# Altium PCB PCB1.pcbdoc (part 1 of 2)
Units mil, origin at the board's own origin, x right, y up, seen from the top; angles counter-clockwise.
Board outline 3622 x 3621.7 mil, 4 copper layers (Top Layer, Inner1, Inner2, Bottom Layer), stack 62.5 mil thick; 107 components, 108 nets, 595 pads, 260 vias.
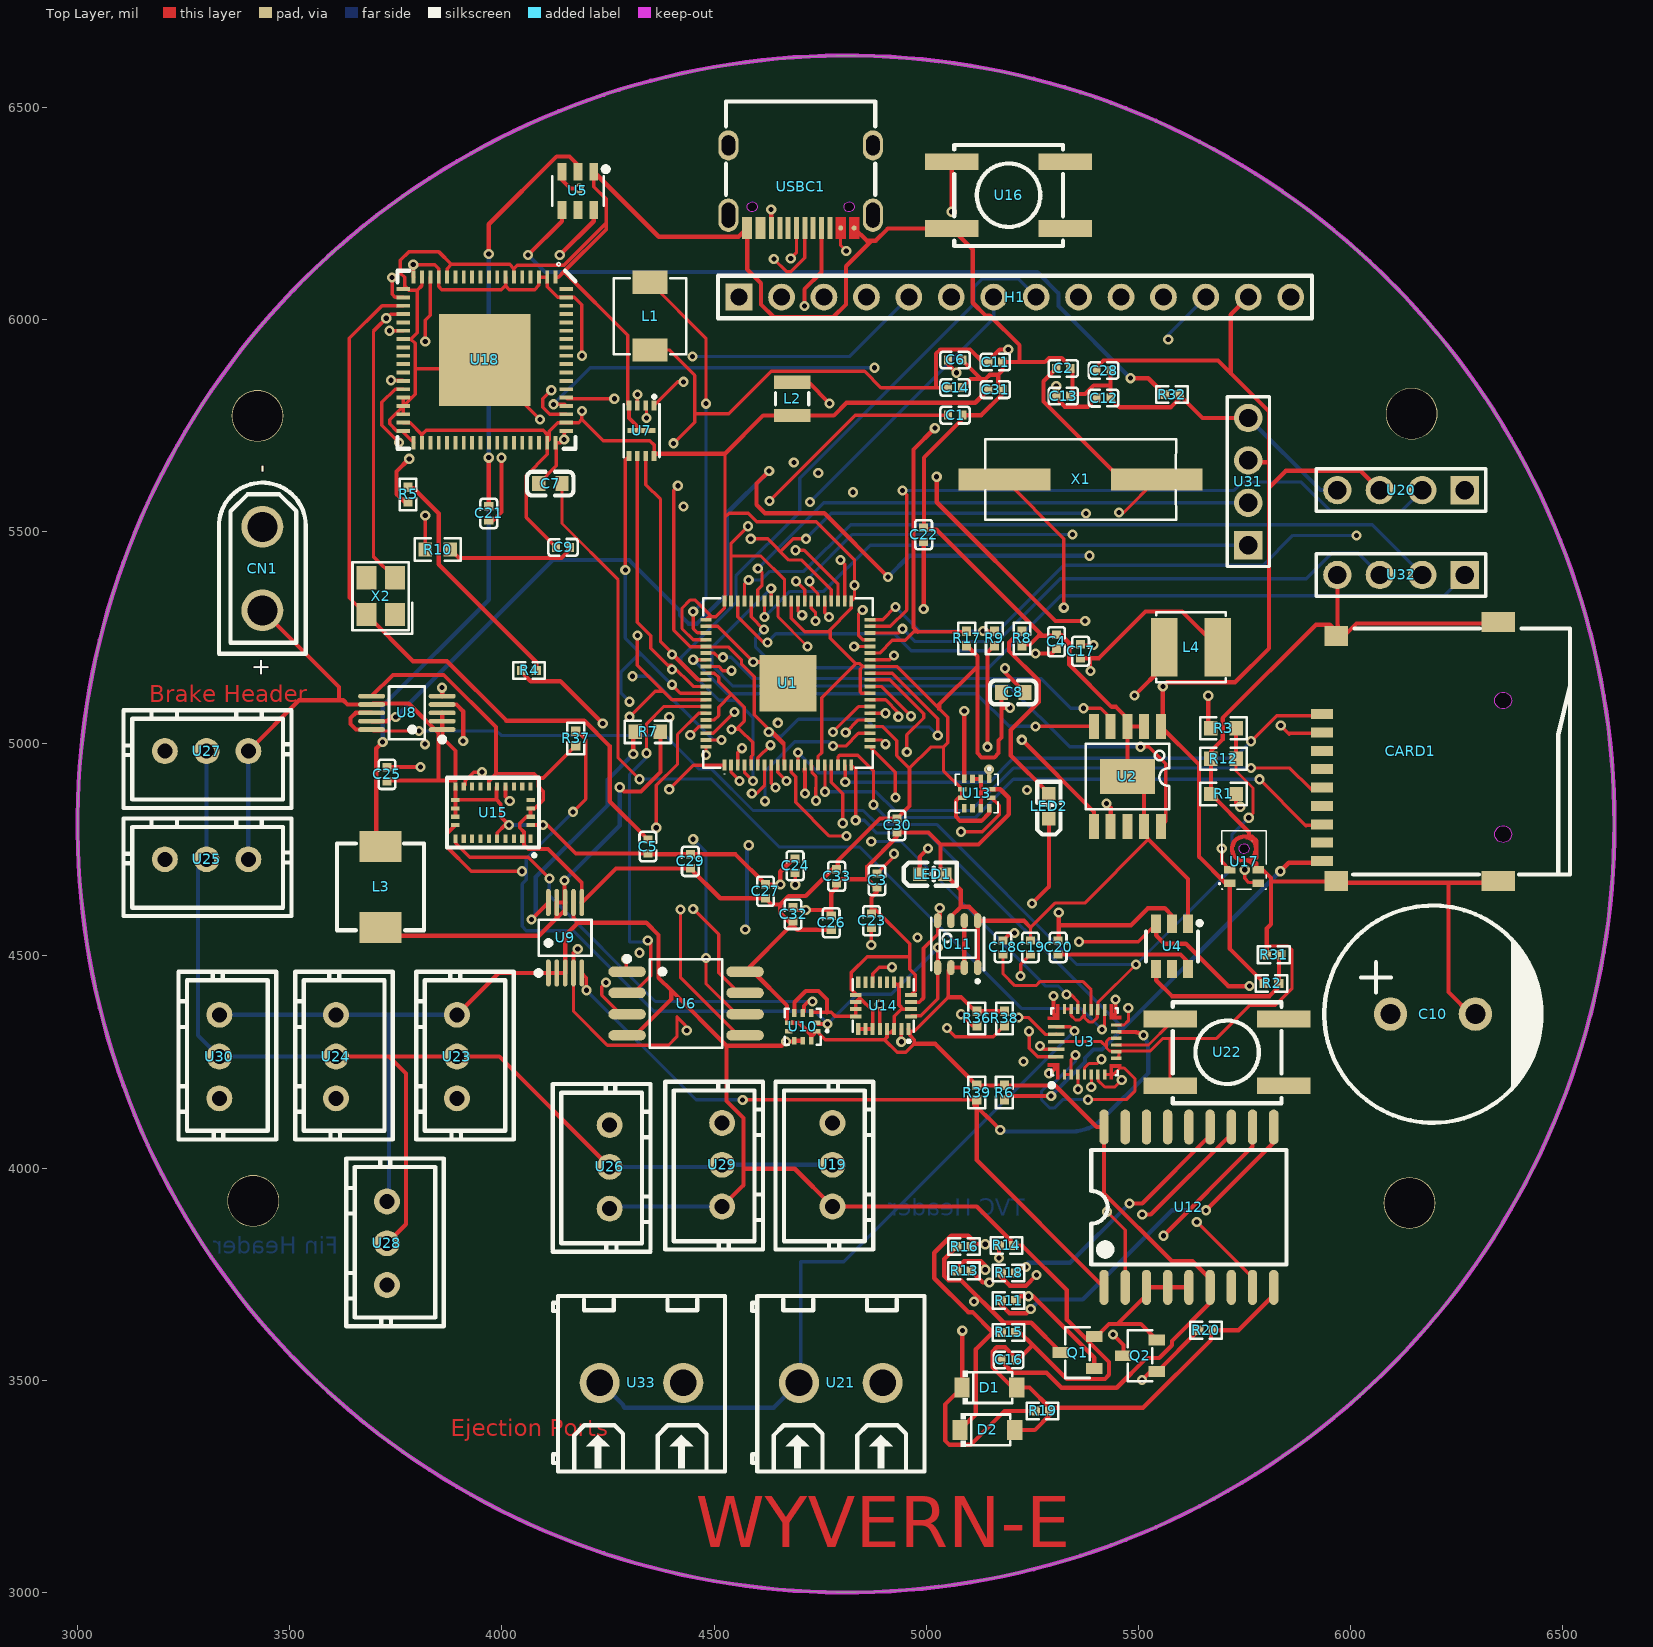
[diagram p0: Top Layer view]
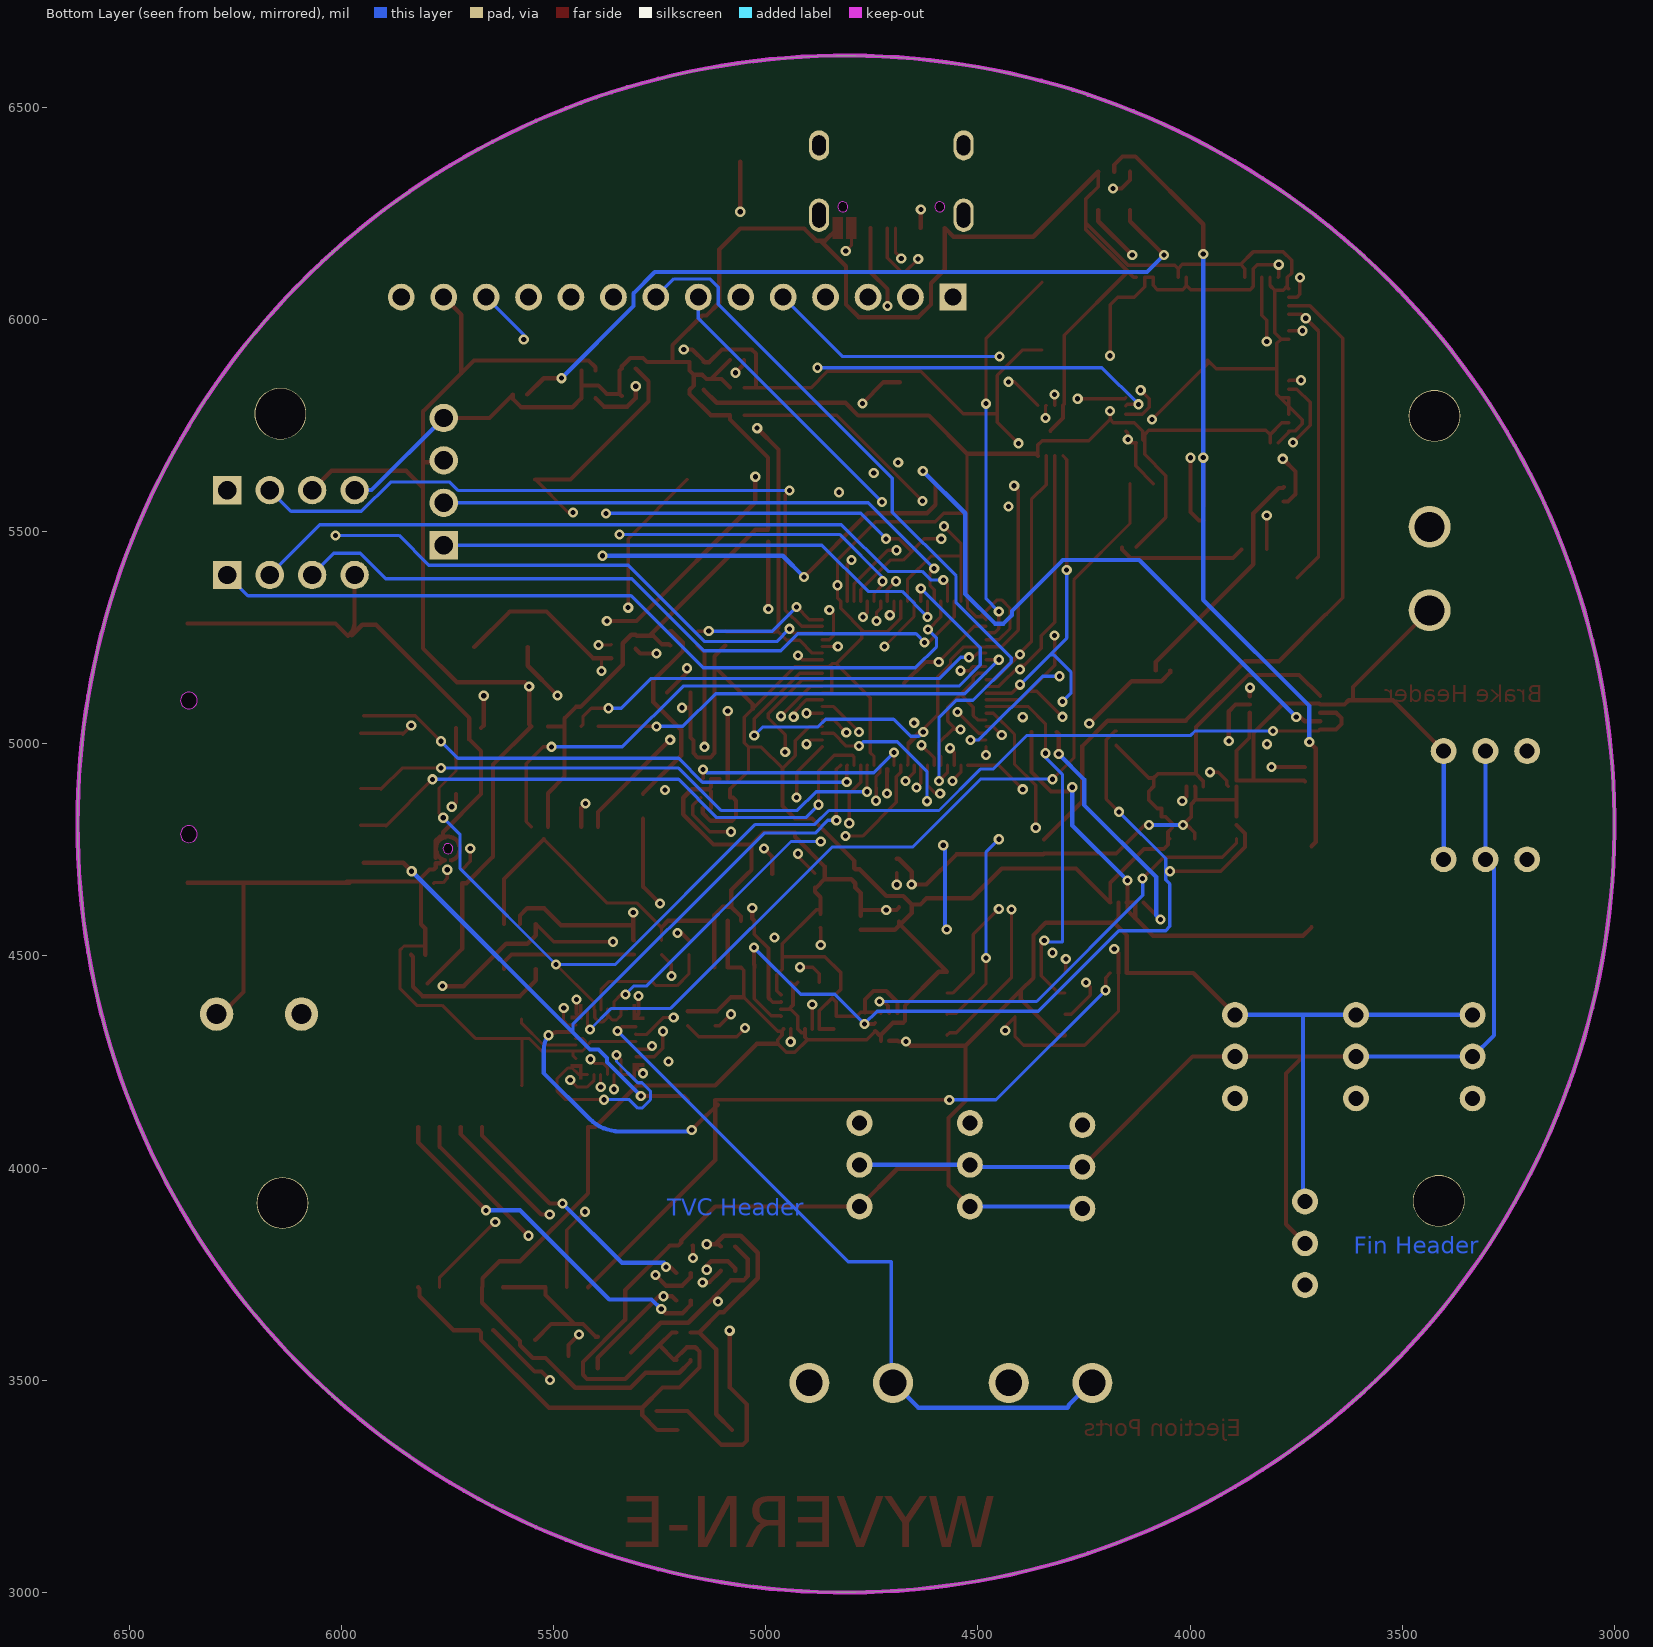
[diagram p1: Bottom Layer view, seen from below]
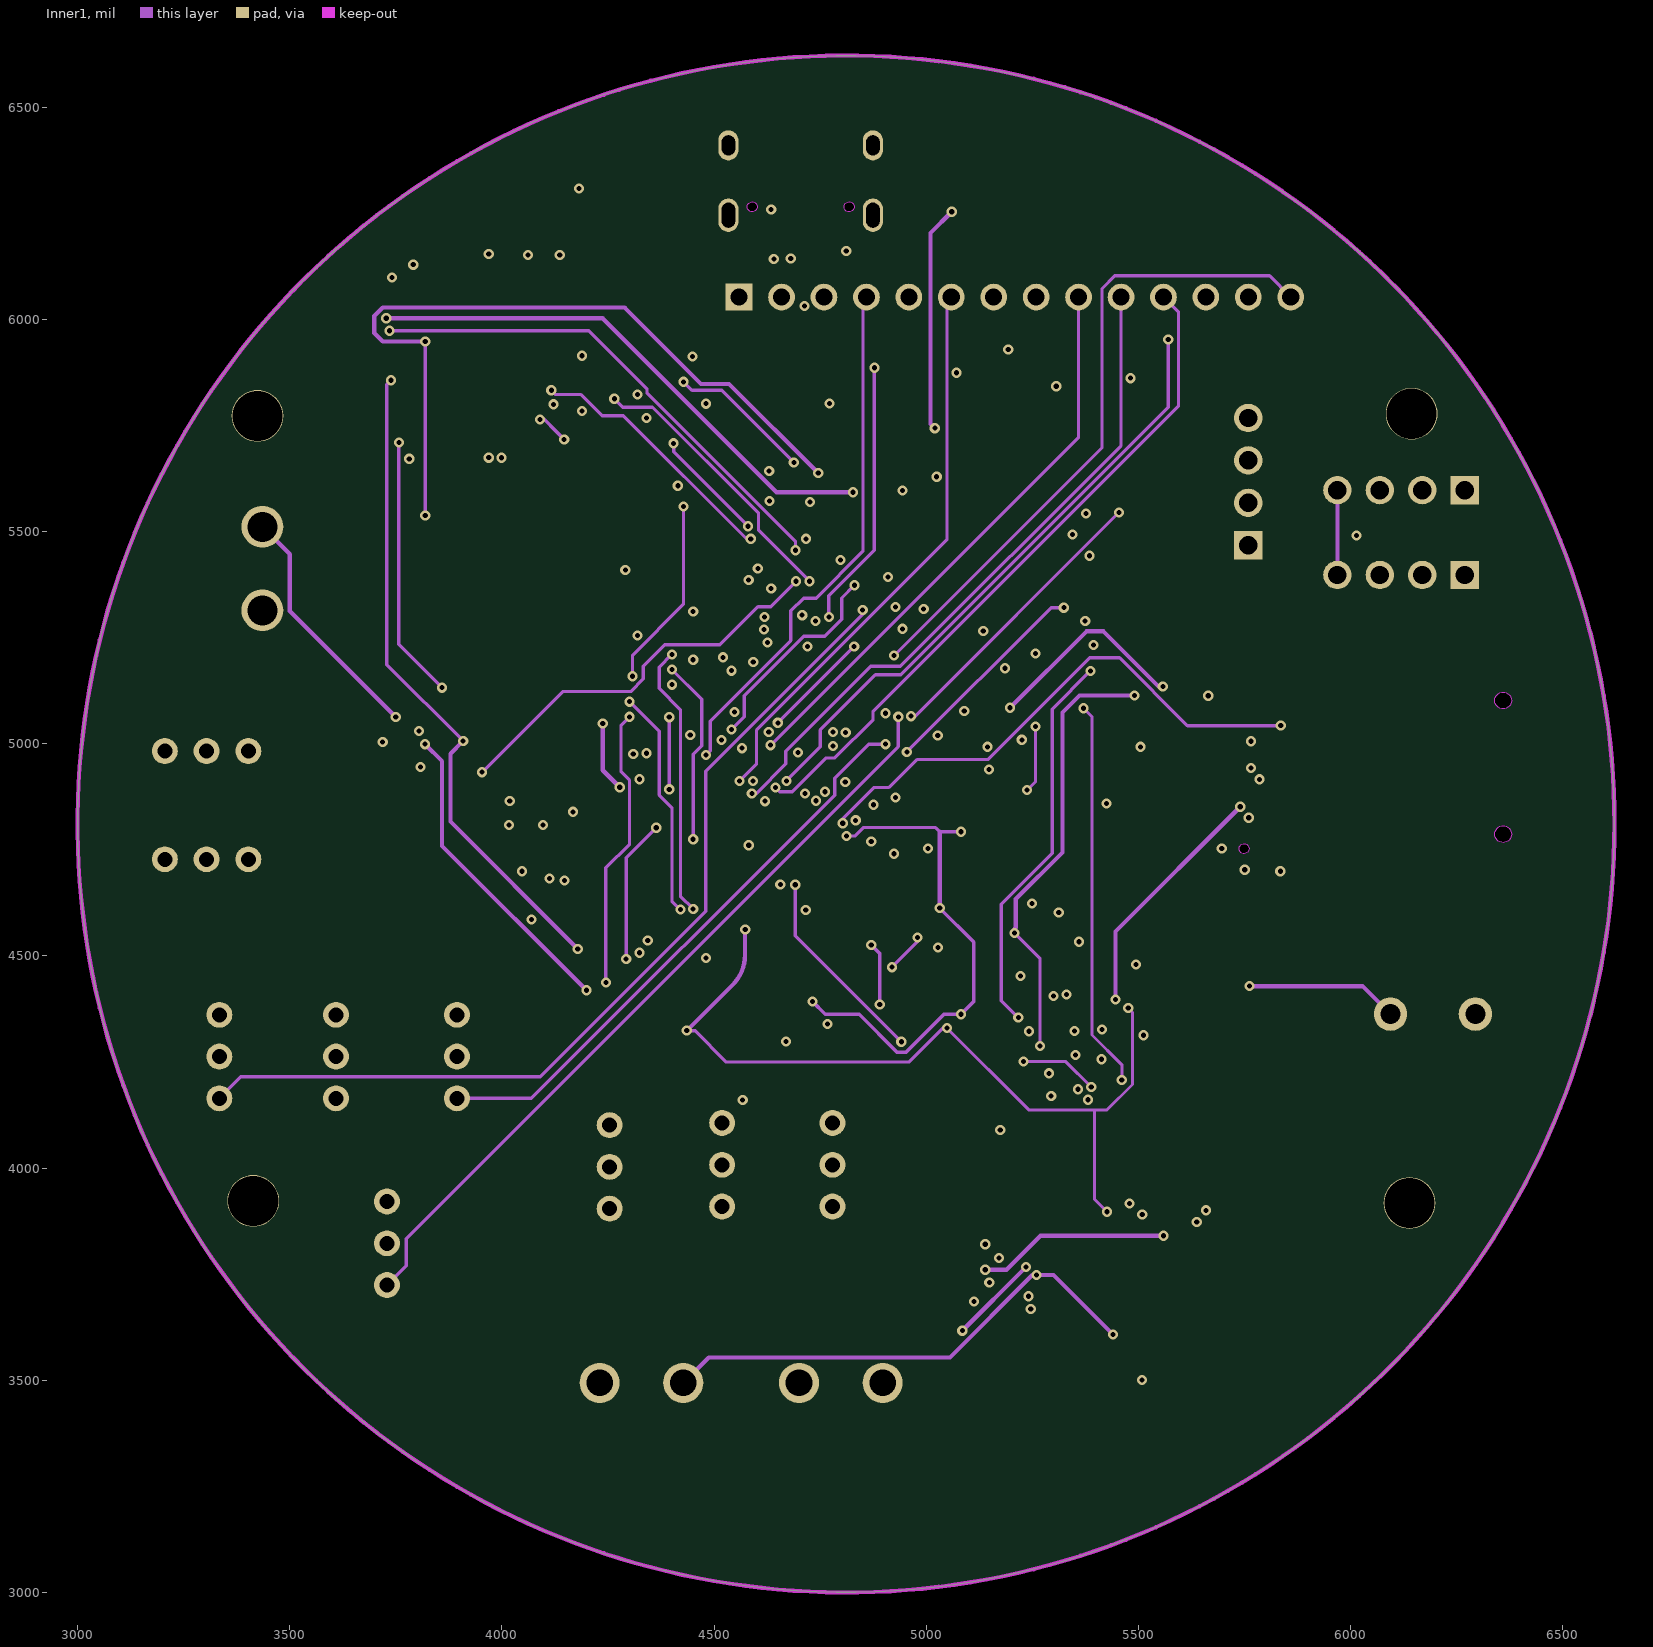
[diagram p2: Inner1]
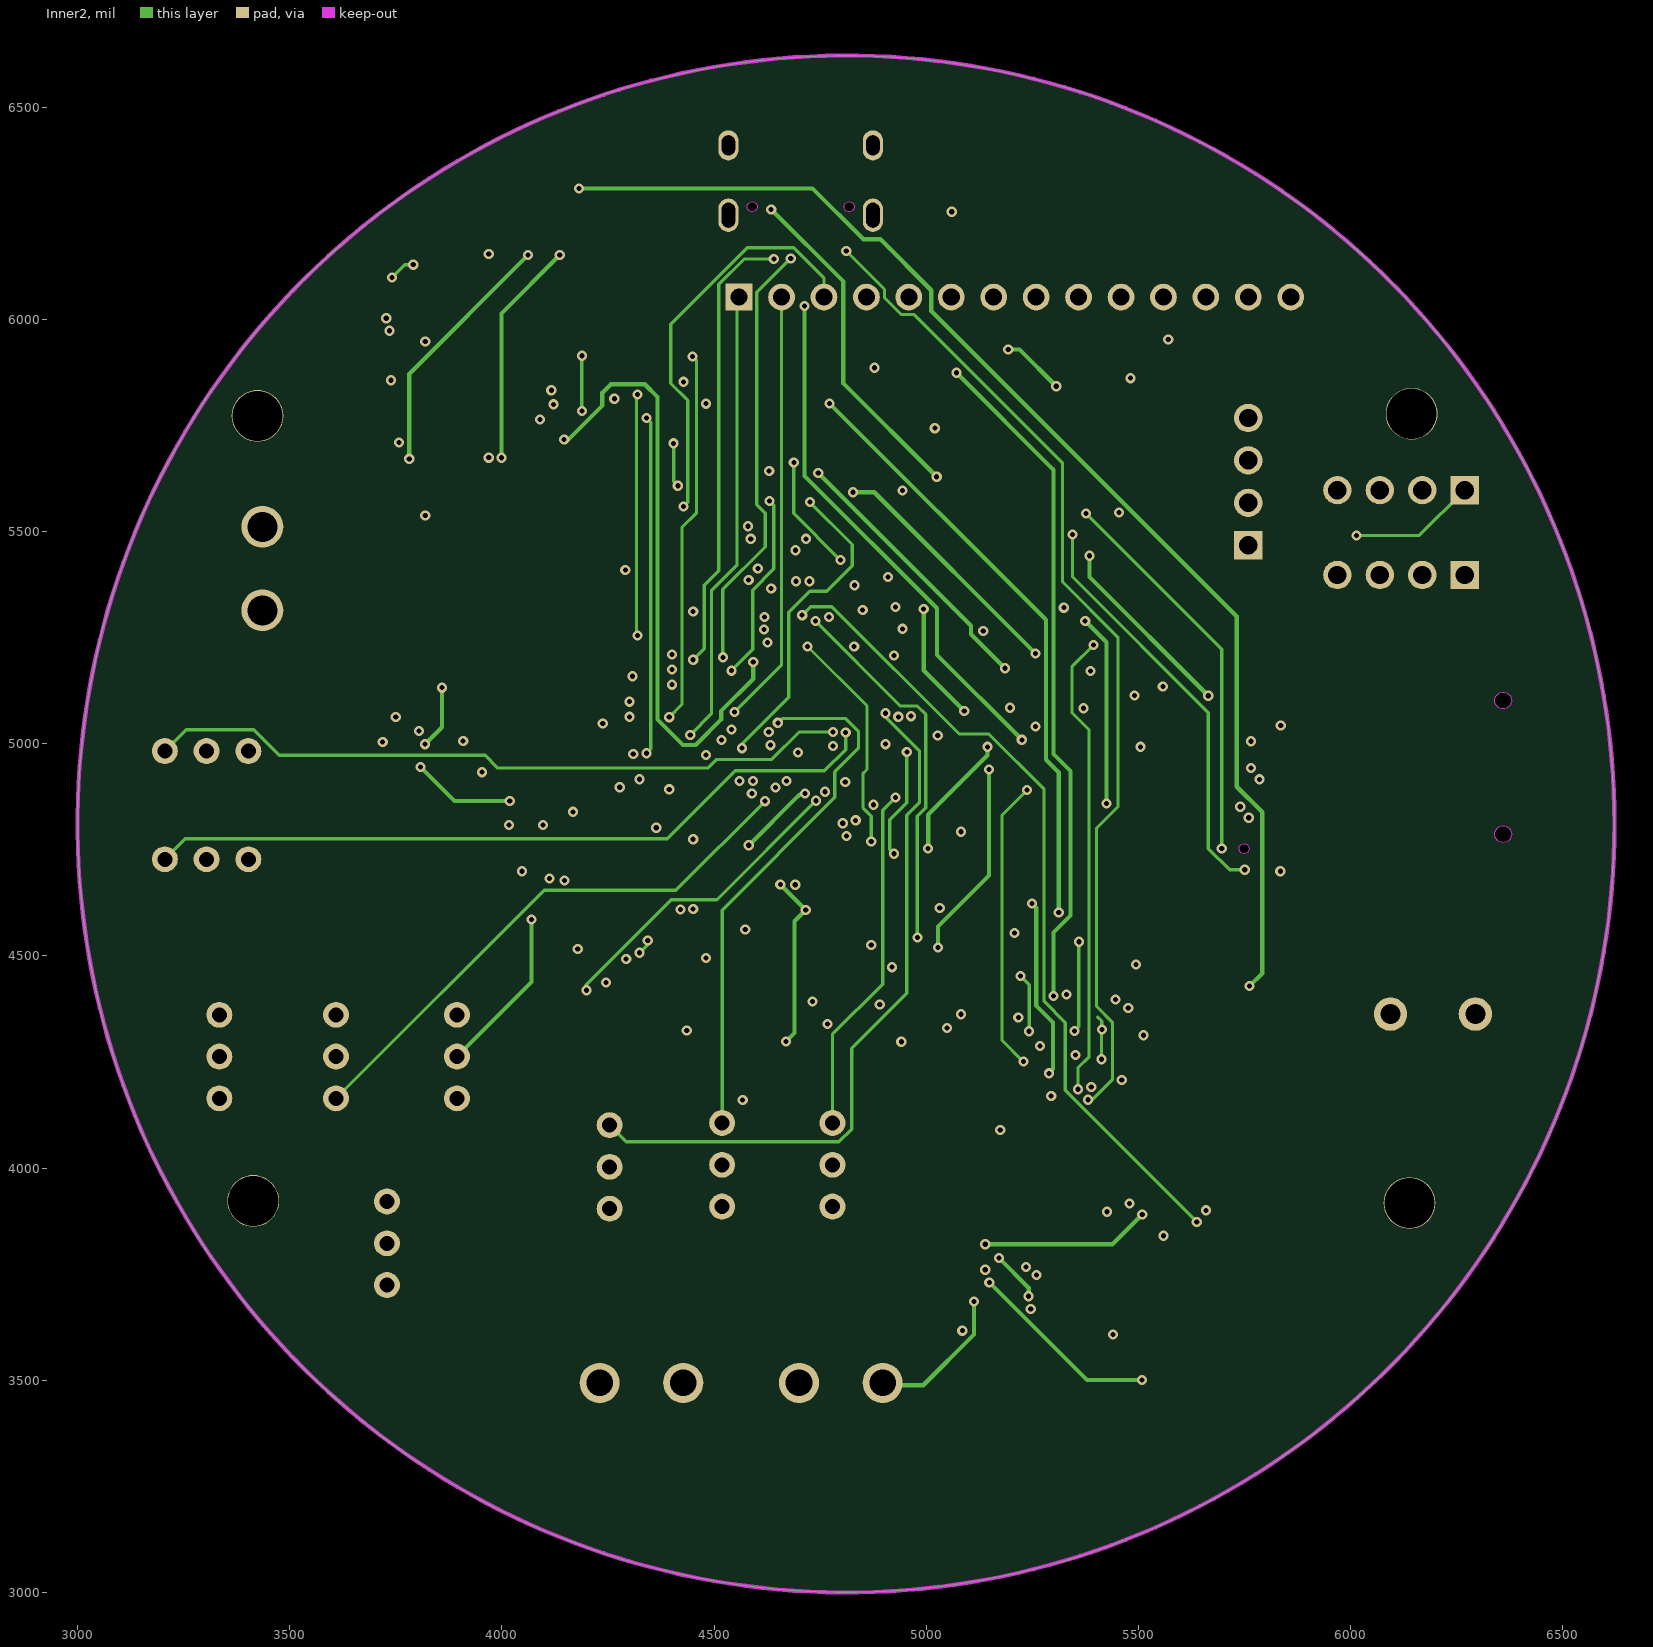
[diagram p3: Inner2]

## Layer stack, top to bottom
Top Layer: signal copper 1.4
Dielectric1: surface 8.3, 7628 RC49% 8.6mil, Dk 0
Inner1: signal copper 0.6
Dielectric2: surface 41.9, 1.1mm H/HOZ Copper, Dk 0
Inner2: signal copper 0.6
Dielectric3: surface 8.3, 7628 RC49% 8.6mil, Dk 0
Bottom Layer: signal copper 1.4

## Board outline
6622,4811 ccw(c4811,4811) 3000,4811 ccw(c4811,4811)

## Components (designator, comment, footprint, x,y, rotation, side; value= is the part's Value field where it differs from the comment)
C1 "100nF" C0402#1 5068,5774.4 r0 top
C2 "18pF" C0402#1 5323,5884.5 r0 top
C3 "18pF" C0402#2 4884.1,4677.9 r270 top
C4 "18pF" C0402#1 5307,5240.5 r90 top
C5 "18pF" C0402#2 4344.1,4757.9 r270 top
C6 "1nF" C0402#1 5068,5904.5 r0 top
C7 "4.7uF" C0603#1 4114.1,5612.9 r180 top
C8 "150pF" C0603#2 5205.2,5121 r0 top
C9 "5.6nF" C0402#3 4144.1,5462.9 r0 top
C10 "2200uF" CAP-TH_BD13.0-P5.00-D1.2-FD 6194.1,4362.9 r0 top
C11 "100nF" C0402#1 5163,5899.5 r0 top
C12 "100nF" C0402#1 5418,5814.6 r0 top
C13 "100nF" C0402#1 5323,5819.5 r0 top
C14 "100nF" C0402#1 5068,5839.4 r0 top
C16 "100nF" C0402#3 5194.1,3547.9 r0 top
C17 "100nF" C0402#2 5364.1,5217.9 r270 top
C18 "100nF" C0402#3 5180.9,4520.1 r90 top
C19 "100nF" C0402#3 5245.9,4520.1 r90 top
C20 "100nF" C0402#3 5311,4520.1 r90 top
C21 "100nF" C0402#1 3969.1,5542.9 r90 top
C22 "100nF" C0402#1 4994.1,5492.9 r90 top
C23 "100nF" C0402#1 4871.2,4583 r90 top
C24 "100nF" C0402#3 4691.2,4712.5 r90 top
C25 "100nF" C0402#2 3729.1,4927.9 r270 top
C26 "100nF" C0402#1 4776.2,4578 r90 top
C27 "100nF" C0402#3 4621.2,4652.5 r90 top
C28 "100nF" C0402#1 5418,5879.6 r0 top
C29 "100nF" C0402#1 4444.1,4722.9 r90 top
C30 "100nF" C0402#3 4931.3,4807.5 r270 top
C31 "100nF" C0402#1 5163,5834.5 r0 top
C32 "100nF" C0402#1 4686.1,4598 r90 top
C33 "100nF" C0402#2 4789.1,4687.9 r270 top
CARD1 "TF-01A" TF-SMD_TF-01A 6140.5,4981.9 r90 top
CN1 "XT30UPB-M" CONN-TH_XT30UPB-M 3435.6,5412.9 r270 top
D1 "BZT52C3V3" SOD-123_L2.7-W1.6-LS3.7-RD 5149.1,3482.9 r0 top
D2 "BZT52C3V3" SOD-123_L2.7-W1.6-LS3.7-RD 5144.1,3382.9 r0 top
H1 "2011-1X14G00SB" HDR-TH_14P-P2.54-V-M_4 5209.1,6052.9 r0 top
L1 "1uH" IND-SMD_L4.4-W4.2 4349.1,6007.9 r90 top
L2 "2.2uH" IND-SMD_L2.5-W2.0_MHCHL2520 4684.1,5812.9 r270 top
L3 "2.2uH" IND-SMD_L5.5-W5.2_NBMC0530N 3714.1,4662.9 r270 top
L4 "3.3uH" IND-SMD_L4.0-W4.0 5624.1,5227.9 r180 top
LED1 "KT-0603R" LED-SMD_L1.6-W0.8-R-RD#1 5014.1,4692.9 r0 top
LED2 "KT-0603R" LED-SMD_L1.6-W0.8-R-RD#2 5289.1,4852.9 r90 top
Q1 "AO3400A" SOT-23-3_L2.9-W1.3-P1.90-LS2.4-BR#1 5356.8,3565.5 r0 top
Q2 "AO3400A" SOT-23-3_L2.9-W1.3-P1.90-LS2.4-BR#2 5504.1,3557.9 r0 top
R1 "NCP18XH103F03RB" R0603#1 5700.6,4881.7 r180 top
R2 "330kΩ" R0402#1 5814.2,4435.3 r0 top
R3 "10mΩ" R0603#1 5700.6,5037.1 r180 top
R4 "680kΩ" R0402#1 4064.1,5172.9 r0 top
R5 "68kΩ" R0402#2 3779.1,5587.9 r270 top
R6 "20kΩ" R0402#2 5184.1,4177.9 r90 top
R7 "10mΩ" R0603#2 4344.1,5027.9 r0 top
R8 "100kΩ" R0402#2 5225.4,5248.4 r270 top
R9 "330Ω" R0402#2 5160.5,5248.4 r270 top
R10 "4.3kΩ" R0603#2 3849.1,5457.9 r0 top
R11 "1kΩ" R0402#1 5194.1,3687.9 r0 top
R12 "100Ω" R0603#1 5700.6,4964.4 r180 top
R13 "1kΩ" R0402#1 5089.1,3757.9 r0 top
R14 "10kΩ" R0402#1 5189.1,3817.9 r0 top
R15 "10kΩ" R0402#1 5194.1,3612.9 r0 top
R16 "33kΩ" R0402#3 5089.1,3815.3 r0 top
R17 "10kΩ" R0402#2 5095.5,5248.4 r270 top
R18 "33kΩ" R0402#1 5194.1,3752.9 r0 top
R19 "10kΩ" R0402#1 5274.1,3427.9 r0 top
R20 "10kΩ" R0402#1 5659.1,3617.9 r0 top
R31 "100kΩ" R0402#1 5819.1,4502.9 r180 top
R32 "100kΩ" R0402#1 5579.1,5822.9 r0 top
R36 "4.7kΩ" R0402#2 5119.3,4352.9 r90 top
R37 "4.7kΩ" R0402#2 4174.1,5012.9 r270 top
R38 "4.7kΩ" R0402#2 5184.2,4352.9 r90 top
R39 "4.7kΩ" R0402#2 5119.1,4177.9 r90 top
U1 "RP2350B" QFN-80_L10.0-W10.0-P0.40-TL-EP3.4 4674.1,5142.9 r90 top
U2 "CH224K" ESSOP-10_L4.9-W3.9-P1.0-LS6.0-TL-EP 5474.1,4922.9 r180 top
U3 "BQ25798RQMR" QFN-29_L4.0-W4.0-P0.40-TL-BQ25792RQMR 5374.1,4297.9 r90 top
U4 "TPS563201DDCR" SOT-23-6_L2.9-W1.6-P0.95-LS2.8-BR 5579.3,4522.4 r90 top
U5 "TPS54202DDCR" SOT-23-6_L2.9-W1.6-P0.95-LS2.8-BL 4179.1,6302.9 r180 top
U6 "W25Q32JVSSIQ" SOIC-8_L5.3-W5.3-P1.27-LS8.0-BL 4434.1,4387.9 r270 top
U7 "APS6404L-3SQR-ZR" USON-8_L3.0-W2.0-P0.50-BL-EP 4329.1,5737.9 r180 top
U8 "INA226AIDGSR" MSOP-10_L3.0-W3.0-P0.50-LS5.0-BL#1 3776.2,5072.9 r90 top
U9 "INA226AIDGSR" MSOP-10_L3.0-W3.0-P0.50-LS5.0-BL#2 4149.1,4542.9 r0 top
U10 "LPS22HBTR" HLGA-10L_LPS22HBTR 4709.1,4332.9 r180 top
U11 "BME680" LGA-8_L3.0-W3.0-P0.80-TR 5074.1,4527.9 r270 top
U12 "MCP23008-E/SO" SOIC-18_L11.6-W7.5-P1.27-LS10.3-BL 5619.1,3907.9 r0 top
U13 "LIS3MDLTR" LGA-12_L2.0-W2.0-P0.50-BL 5119.1,4882.9 r180 top
U14 "LSM9DS1TR" LGA-24_L3.5-W3.0-P0.43-TL 4899.1,4382.9 r180 top
U15 "BNO055" LGA-28_L5.2-W3.8-P0.50-BL 3979.1,4837.9 r90 top
U16 "EVQ-Q2P02W" SW-SMD_4P-L6.5-W6.0-P4.00-LS6.6-TL 5194.1,6292.9 r0 top
U17 "IM63D135AXTMA1" MIC-SMD_5P-L3.5-W2.7_IM66D130AXTMA1 5749.1,4722.9 r0 top
U18 "ADAU1450WBCPZ-RL" LFCSP-72_L10.0-W9.8-P0.50-LS10.2-TL-EP5.5 3959.5,5904.5 r270 top
U19 "B3B-XH-A(LF)(SN)" CONN-TH_3P-P2.50_A2501WV2-3P#1 4779.1,4007.9 r270 top
U20 "2.54-1*4" HDR-TH_4P-P2.54-V-M-1 6119.1,5597.9 r180 top
U21 "KF128-5.0-2P" CONN-TH_P5.00_KF128-5.0-2P 4798.9,3493.9 r0 top
U22 "EVQ-Q2P02W" SW-SMD_4P-L6.5-W6.0-P4.00-LS6.6-TL 5709.1,4272.9 r0 top
U23 "B3B-XH-A(LF)(SN)" CONN-TH_3P-P2.50_A2501WV2-3P#2 3894.1,4262.9 r90 top
U24 "B3B-XH-A(LF)(SN)" CONN-TH_3P-P2.50_A2501WV2-3P#2 3609.1,4262.9 r90 top
U25 "B3B-XH-A(LF)(SN)" CONN-TH_3P-P2.50_A2501WV2-3P#3 3304.1,4727.9 r0 top
U26 "B3B-XH-A(LF)(SN)" CONN-TH_3P-P2.50_A2501WV2-3P#1 4254.1,4002.9 r270 top
U27 "B3B-XH-A(LF)(SN)" CONN-TH_3P-P2.50_A2501WV2-3P#3 3304.1,4982.9 r0 top
U28 "B3B-XH-A(LF)(SN)" CONN-TH_3P-P2.50_A2501WV2-3P#2 3729.1,3822.9 r90 top
U29 "B3B-XH-A(LF)(SN)" CONN-TH_3P-P2.50_A2501WV2-3P#1 4519.1,4007.9 r270 top
U30 "B3B-XH-A(LF)(SN)" CONN-TH_3P-P2.50_A2501WV2-3P#2 3334.1,4262.9 r90 top
U31 "2.54-1*4" HDR-TH_4P-P2.54-V-M-1 5759.1,5617.9 r90 top
U32 "2.54-1*4" HDR-TH_4P-P2.54-V-M-1 6119.1,5397.9 r180 top
U33 "KF128-5.0-2P" CONN-TH_P5.00_KF128-5.0-2P 4328.9,3493.9 r0 top
USBC1 "TYPE-C-31-M-12" USB-C_SMD-TYPE-C-31-M-12_1 4704.1,6312.9 r180 top
X1 "12MHz" HC-49S_L11.4-W4.8 5364.1,5622.9 r0 top
X2 "-" CRYSTAL-SMD_4P-L3.2-W2.5-BL 3714.1,5347.9 r90 top

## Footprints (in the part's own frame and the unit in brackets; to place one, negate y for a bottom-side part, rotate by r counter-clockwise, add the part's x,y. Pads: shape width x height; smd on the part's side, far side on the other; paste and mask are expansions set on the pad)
C0402#1 [mil]
  rect 19.7x21.3 smd: 1(-16.5,0) 2(16.6,0)
  silkscreen extent -34,-20 34,20
C0402#2 [mil]
  rect 19.7x21.3 smd: 1(-16.6,0) 2(16.5,0)
  silkscreen extent -34,-20 34,20
C0402#3 [mil]
  rect 19.7x21.3 smd: 1(-16.5,0) 2(16.5,0)
  silkscreen extent -34,-20 34,20
C0603#1 [mil]
  rect 31.5x35.4 smd: 1(-27.6,0) 2(27.6,0)
  silkscreen extent -55,-28 55,28
C0603#2 [mil]
  rect 31.5x35.4 smd: 1(-27.6,0) 2(27.5,0)
  silkscreen extent -55,-28 55,28
CAP-TH_BD13.0-P5.00-D1.2-FD [mil]
  round 78.7 hole 47.2: 1(-100,0) 2(100,0)
  silkscreen extent -256,-256 256,256
CONN-TH_3P-P2.50_A2501WV2-3P#1 [mil]
  round 61 hole 35.4: 1(-98.5,0) 2(0,0) 3(98.4,0)
  silkscreen extent -195,-134 200,96
CONN-TH_3P-P2.50_A2501WV2-3P#2 [mil]
  round 61 hole 35.4: 1(-98.4,0) 2(0,0) 3(98.5,0)
  silkscreen extent -195,-134 200,96
CONN-TH_3P-P2.50_A2501WV2-3P#3 [mil]
  round 61 hole 35.4: 1(-98.4,0) 2(0,0) 3(98.4,0)
  silkscreen extent -196,-134 200,96
CONN-TH_P5.00_KF128-5.0-2P [mil]
  round 94.5 hole 63: 1(-98.4,0) 2(98.5,0)
  silkscreen extent -209,-209 197,205
CONN-TH_XT30UPB-M [mil]
  round 98.4 hole 70.9: 1(-98.5,0) 2(98.4,0)
  silkscreen extent -203,-102 201,102
CRYSTAL-SMD_4P-L3.2-W2.5-BL [mil]
  rect 55.1x47.2 smd: 1(-43.3,-33.5) 2(43.3,-33.5) 3(43.3,33.5) 4(-43.3,33.5)
  silkscreen extent -89,-75 80,66
ESSOP-10_L4.9-W3.9-P1.0-LS6.0-TL-EP [mil]
  rect 23.6x59.1 smd paste+0 mask+2: 1(-78.7,-118.1) 2(-39.4,-118.1) 3(0,-118.1) 4(39.4,-118.1) 5(78.7,-118.1) 6(78.7,118.1) 7(39.4,118.1) 8(0,118.1) 9(-39.4,118.1) 10(-78.7,118.1)
  rect 129.9x82.7 smd paste+0 mask+2: 11(0,0)
  silkscreen extent -98,-77 98,77
HC-49S_L11.4-W4.8 [mil]
  rect 216.5x51.2 smd: 1(-179.2,0) 2(179.3,0)
  silkscreen extent -225,-95 225,95
HDR-TH_4P-P2.54-V-M-1 [mil]
  rect 66.9x66.9 hole 43.3: 1(-150,0)
  round 66.9 hole 43.3: 2(-50,0) 3(50,0) 4(150,0)
  silkscreen extent -200,-50 200,50
HDR-TH_14P-P2.54-V-M_4 [mil]
  rect 63x63 hole 40.2: 1(-650,0)
  round 63 hole 40.2: 2(-550,0) 3(-450,0) 4(-350,0) 5(-250,0) 6(-150,0) 7(-50,0) 8(50,0) 9(150,0) 10(250,0) 11(350,0) 12(450,0) 13(550,0) 14(650,0)
  silkscreen extent -700,-50 700,50
HLGA-10L_LPS22HBTR [mil]
  rect 18.3x11 smd: 1(-32.8,10) 2(-32.8,-9.7) 6(32.8,-9.7) 7(32.8,10)
  rect 11x18.3 smd: 3(-19.7,-32.6) 4(0,-32.6) 5(19.7,-32.6) 8(19.7,32.5) 9(0,32.5) 10(-19.7,32.5)
  silkscreen extent -60,-42 42,43
IND-SMD_L2.5-W2.0_MHCHL2520 [mil]
  rect 31.5x86.6 smd: 1(-39.4,0) 2(39.3,0)
  silkscreen extent -15,-39 15,39
IND-SMD_L4.0-W4.0 [mil]
  rect 63x137.8 smd: 1(-63,0) 2(63,0)
  silkscreen extent -82,-83 82,83
IND-SMD_L4.4-W4.2 [mil]
  rect 55.1x83.5 smd: 1(79.9,0) 2(-79.8,0)
  silkscreen extent -90,-86 90,86
IND-SMD_L5.5-W5.2_NBMC0530N [mil]
  rect 72.8x98.4 smd: 1(-95.5,0) 2(95.4,0)
  silkscreen extent -102,-102 102,102
LED-SMD_L1.6-W0.8-R-RD#1 [mil]
  rect 31.5x31.5 smd: 1(29.5,0) 2(-29.5,0)
  silkscreen extent -67,-28 58,28
LED-SMD_L1.6-W0.8-R-RD#2 [mil]
  rect 31.5x31.5 smd: 1(29.6,0) 2(-29.5,0)
  silkscreen extent -67,-28 58,28
LFCSP-72_L10.0-W9.8-P0.50-LS10.2-TL-EP5.5 [mil]
  rect 31.5x9.1 smd paste-3937 mask+2: 1(-195.5,167.3) 2(-195.5,147.6) 3(-195.5,127.9) 4(-195.5,108.2) 5(-195.5,88.5) 6(-195.5,68.9) 7(-195.5,49.2) 8(-195.5,29.5) 9(-195.5,9.8) 10(-195.5,-9.9) 11(-195.5,-29.6) 12(-195.5,-49.2) 13(-195.5,-68.9) 14(-195.5,-88.6) 15(-195.5,-108.3) 16(-195.5,-128) 17(-195.5,-147.7) 18(-195.5,-167.4) 37(195.4,-167.4) 38(195.4,-147.7) 39(195.4,-128) 40(195.4,-108.3) 41(195.4,-88.6) 42(195.4,-68.9) 43(195.4,-49.3) 44(195.4,-29.6) 45(195.4,-9.9) 46(195.4,9.8) 47(195.4,29.5) 48(195.4,49.2) 49(195.4,68.9) 50(195.4,88.5) 51(195.4,108.2) 52(195.4,127.9) 53(195.4,147.6) 54(195.4,167.3)
  rect 9.1x31.5 smd paste-3937 mask+2: 19(-167.4,-192.2) 20(-147.7,-192.2) 21(-128,-192.2) 22(-108.3,-192.2) 23(-88.6,-192.2) 24(-68.9,-192.2) 25(-49.3,-192.2) 26(-29.6,-192.2) 27(-9.9,-192.2) 28(9.8,-192.2) 29(29.5,-192.2) 30(49.2,-192.2) 31(68.8,-192.2) 32(88.5,-192.2) 33(108.2,-192.2) 34(127.9,-192.2) 35(147.6,-192.2) 36(167.3,-192.2) 55(167.3,192.1) 56(147.6,192.1) 57(127.9,192.1) 58(108.2,192.1) 59(88.5,192.1) 60(68.8,192.1) 61(49.2,192.1) 62(29.5,192.1) 63(9.8,192.1) 64(-9.9,192.1) 65(-29.6,192.1) 66(-49.3,192.1) 67(-68.9,192.1) 68(-88.6,192.1) 69(-108.3,192.1) 70(-128,192.1) 71(-147.7,192.1) 72(-167.4,192.1)
  rect 216.5x216.5 smd paste-3937 mask+2: 73(0,0)
  silkscreen extent -230,-206 209,214
LGA-8_L3.0-W3.0-P0.80-TR [mil]
  oval 35.4x17.6 smd: 1(55.1,47.2) 2(55.1,15.8) 3(55.1,-15.7) 4(55.1,-47.2) 5(-55.2,-47.2) 6(-55.2,-15.7) 7(-55.2,15.8) 8(-55.2,47.2)
  silkscreen extent -62,-62 92,62
LGA-12_L2.0-W2.0-P0.50-BL [mil]
  rect 11x19.7 smd: 1(-29.5,-34.5) 2(-9.8,-34.5) 3(9.8,-34.5) 4(29.5,-34.5) 7(29.5,34.4) 8(9.8,34.4) 9(-9.8,34.4) 10(-29.5,34.4)
  rect 19.7x11 smd: 5(34.4,-9.9) 6(34.4,9.8) 11(-34.5,9.8) 12(-34.5,-9.9)
  silkscreen extent -50,-60 50,45
LGA-24_L3.5-W3.0-P0.43-TL [mil]
  rect 9.5x27.6 smd: 1(-59.3,55.1) 6(-59.3,-55.2) 7(-42.3,-55.2) 8(-25.4,-55.2) 9(-8.5,-55.2) 10(8.5,-55.2) 11(25.4,-55.2) 12(42.3,-55.2) 13(59.2,-55.2) 18(59.2,55.1) 19(42.3,55.1) 20(25.4,55.1) 21(8.5,55.1) 22(-8.5,55.1) 23(-25.4,55.1) 24(-42.3,55.1)
  rect 27.6x9.5 smd: 2(-65,25.4) 3(-65,8.4) 4(-65,-8.5) 5(-65,-25.4) 14(65,-25.4) 15(65,-8.5) 16(65,8.4) 17(65,25.4)
  silkscreen extent -72,-62 72,87
LGA-28_L5.2-W3.8-P0.50-BL [mil]
  rect 19.7x9.8 smd: 1(-61.5,-88.6) 6(61.6,-88.6) 7(61.6,-68.9) 8(61.6,-49.2) 9(61.6,-29.5) 10(61.6,-9.8) 11(61.6,9.8) 12(61.6,29.5) 13(61.6,49.2) 14(61.6,68.9) 15(61.6,88.6) 20(-61.5,88.6) 21(-61.5,68.9) 22(-61.5,49.2) 23(-61.5,29.5) 24(-61.5,9.8) 25(-61.5,-9.8) 26(-61.5,-29.5) 27(-61.5,-49.2) 28(-61.5,-68.9)
  rect 9.8x19.7 smd: 2(-29.5,-88.6) 3(-9.8,-88.6) 4(9.9,-88.6) 5(29.6,-88.6) 16(29.6,88.6) 17(9.9,88.6) 18(-9.8,88.6) 19(-29.5,88.6)
  silkscreen extent -105,-108 82,108
MIC-SMD_5P-L3.5-W2.7_IM66D130AXTMA1 [mil]
  rect 27.6x17.7 smd paste+0 mask+2: 1(-33.5,-51.6) 2(-33.5,-19.3) 3(33.5,-51.6) 4(33.5,-19.3)
  round 1.6 smd: 5(-18,10.9) 5(-17.6,48.8) 5(18,10.9) 5(18.4,48)
  Top Layer region: 22.6,33.8 22.6,35.1 22.5,36.3 22.3,37.6 22,38.8 21.6,40 21.1,41.2 20.6,42.3 19.9,43.4 19.3,44.5 18.5,45.5 17.7,46.4 16.8,47.3 15.8,48.2 14.8,48.9 13.8,49.6 12.7,50.2 11.5,50.8 10.3,51.2 9.1,51.6 7.9,51.9 6.7,52.1 5.4,52.3 4.1,52.3 3.7,52.3 3.7,59.4 4.5,59.4 6,59.4 7.4,59.2 8.8,59 10.2,58.8 11.6,58.4 13,58 14.3,57.5 15.6,56.9 16.9,56.2 18.1,55.5 19.3,54.7 20.5,53.8 21.6,52.9 22.6,51.9 23.6,50.9 24.5,49.8 25.4,48.6 26.2,47.4 26.9,46.2 27.6,44.9 28.2,43.6 28.7,42.3 29.1,40.9 29.5,39.5 29.8,38.1 30,36.7 30.1,35.2 30.1,33.8 29.3,33.8
  Top Layer region: -3.4,53.1 -4.6,53 -5.9,52.9 -7.1,52.7 -8.4,52.4 -9.6,52 -10.8,51.5 -11.9,51 -13,50.4 -14.1,49.7 -15.1,48.9 -16,48.1 -16.9,47.2 -17.7,46.2 -18.5,45.2 -19.2,44.2 -19.8,43.1 -20.4,41.9 -20.8,40.8 -21.2,39.5 -21.5,38.3 -21.7,37.1 -21.8,35.8 -21.9,34.6 -21.9,34.2 -29,34.2 -29,34.9 -28.9,36.4 -28.8,37.8 -28.6,39.2 -28.3,40.6 -28,42 -27.5,43.4 -27,44.7 -26.4,46.1 -25.8,47.3 -25.1,48.6 -24.3,49.8 -23.4,50.9 -22.5,52 -21.5,53 -20.4,54 -19.3,55 -18.2,55.8 -17,56.6 -15.8,57.3 -14.5,58 -13.2,58.6 -11.8,59.1 -10.5,59.5 -9.1,59.9 -7.7,60.2 -6.2,60.4 -4.8,60.5 -3.4,60.5 -3.4,59.7
  Top Layer region: -22.2,25.1 -22.2,23.8 -22.1,22.5 -21.9,21.3 -21.6,20.1 -21.2,18.9 -20.7,17.7 -20.2,16.5 -19.5,15.4 -18.9,14.4 -18.1,13.4 -17.3,12.4 -16.4,11.5 -15.4,10.7 -14.4,9.9 -13.3,9.3 -12.2,8.6 -11.1,8.1 -9.9,7.6 -8.7,7.2 -7.5,6.9 -6.3,6.7 -5,6.6 -3.7,6.6 -3.3,6.6 -3.3,-0.5 -4.1,-0.5 -5.6,-0.5 -7,-0.4 -8.4,-0.2 -9.8,0.1 -11.2,0.5 -12.6,0.9 -13.9,1.4 -15.2,2 -16.5,2.7 -17.7,3.4 -18.9,4.2 -20.1,5.1 -21.2,6 -22.2,7 -23.2,8 -24.1,9.1 -25,10.3 -25.8,11.4 -26.5,12.7 -27.2,14 -27.8,15.3 -28.3,16.6 -28.7,18 -29.1,19.4 -29.4,20.8 -29.6,22.2 -29.7,23.6 -29.7,25.1 -28.9,25.1
  Top Layer region: 3.8,6.6 5.1,6.6 6.3,6.8 7.6,7 8.8,7.3 10,7.7 11.2,8.1 12.3,8.7 13.4,9.3 14.5,10 15.5,10.7 16.4,11.6 17.3,12.5 18.1,13.4 18.9,14.4 19.6,15.5 20.2,16.6 20.8,17.7 21.2,18.9 21.6,20.1 21.9,21.3 22.1,22.6 22.2,23.8 22.3,25.1 22.3,25.5 29.4,25.5 29.4,24.7 29.3,23.3 29.2,21.8 29,20.4 28.7,19 28.4,17.6 27.9,16.3 27.4,14.9 26.8,13.6 26.2,12.3 25.5,11.1 24.7,9.9 23.8,8.8 22.9,7.7 21.9,6.6 20.8,5.6 19.7,4.7 18.6,3.8 17.4,3 16.2,2.3 14.9,1.7 13.6,1.1 12.2,0.6 10.9,0.1 9.5,-0.2 8.1,-0.5 6.7,-0.7 5.2,-0.8 3.8,-0.9 3.8,-0.1
  Board Outline Layer lines w0.1: -11.7,28.6 -11,25.7 -9.5,23.1 -7.5,20.9 -5,19.3 -2.2,18.4 0.7,18.2 3.7,18.8 6.3,20.1 8.6,21.9 10.4,24.3 11.4,27.1 11.8,30 11.4,33 10.4,35.7 8.6,38.1 6.3,40 3.7,41.3 0.7,41.8 -2.2,41.6 -5,40.7 -7.5,39.1 -9.5,37 -11,34.4 -11.7,31.5 -11.7,28.6
  Board Outline Layer region: 11.8,30 11.4,27.1 10.4,24.3 8.6,21.9 6.3,20.1 3.7,18.8 0.7,18.2 -2.2,18.4 -5,19.3 -7.5,20.9 -9.5,23.1 -11,25.7 -11.7,28.6 -11.7,31.5 -11,34.4 -9.5,37 -7.5,39.1 -5,40.7 -2.2,41.6 0.7,41.8 3.7,41.3 6.3,40 8.6,38.1 10.4,35.7 11.4,33
  Board Outline Layer region: 11.8,30 11.4,27.1 10.4,24.3 8.6,21.9 6.3,20.1 3.7,18.8 0.7,18.2 -2.2,18.4 -5,19.3 -7.5,20.9 -9.5,23.1 -11,25.7 -11.7,28.6 -11.7,31.5 -11,34.4 -9.5,37 -7.5,39.1 -5,40.7 -2.2,41.6 0.7,41.8 3.7,41.3 6.3,40 8.6,38.1 10.4,35.7 11.4,33
  Multi-Layer board cut-out: 11.8,30 11.4,27.1 10.4,24.3 8.6,21.9 6.3,20.1 3.7,18.8 0.7,18.2 -2.2,18.4 -5,19.3 -7.5,20.9 -9.5,23.1 -11,25.7 -11.7,28.6 -11.7,31.5 -11,34.4 -9.5,37 -7.5,39.1 -5,40.7 -2.2,41.6 0.7,41.8 3.7,41.3 6.3,40 8.6,38.1 10.4,35.7 11.4,33
  silkscreen extent -60,-66 52,72
MSOP-10_L3.0-W3.0-P0.50-LS5.0-BL#1 [mil]
  oval 11x63.8 smd: 1(-39.3,-83.1) 2(-19.6,-83.1) 3(0,-83.1) 4(19.7,-83.1) 5(39.4,-83.1) 6(39.4,83.1) 7(19.7,83.1) 8(0,83.1) 9(-19.6,83.1) 10(-39.3,83.1)
  silkscreen extent -69,-89 62,42
MSOP-10_L3.0-W3.0-P0.50-LS5.0-BL#2 [mil]
  oval 11x63.8 smd: 1(-39.4,-83) 2(-19.7,-83) 3(0,-83) 4(19.7,-83) 5(39.4,-83) 6(39.4,83.1) 7(19.7,83.1) 8(0,83.1) 9(-19.7,83.1) 10(-39.4,83.1)
  silkscreen extent -69,-89 62,42
QFN-29_L4.0-W4.0-P0.40-TL-BQ25792RQMR [mil]
  round 0 smd: 1(-69.8,73.8) 9(-70.8,-71.9) 16(70.9,-71.9) 24(69.9,73.8)
  rect 23.6x7.9 smd: 2(-76.7,48.2) 3(-76.7,32.5) 4(-76.7,16.7) 5(-76.7,1) 6(-76.7,-14.8) 7(-76.7,-30.5) 8(-76.7,-46.3) 20(76.8,1) 21(76.8,16.7) 22(76.8,32.5) 23(76.8,48.2)
  rect 7.9x23.6 smd: 10(-39.3,-73.8) 11(-23.6,-73.8) 12(-7.8,-73.8) 13(7.9,-73.8) 14(23.6,-73.8) 15(39.4,-73.8)
  rect 27.6x7.9 smd: 17(74.8,-46.3)
  rect 25.6x7.9 smd: 18(75.8,-30.5)
  rect 26.8x7.9 smd: 19(75.2,-14.8)
  rect 8.7x39.4 smd: 25(35.5,67.9) 26(17.8,67.9) 27(0,67.9) 28(-17.7,67.9)
  rect 8.7x37.4 smd: 29(-35.4,68.9)
  Top Layer region: 88.6,-66 88.6,-58.1 61.1,-58.1 53.2,-58.1 53.2,-58.1 53.2,-66 53.2,-66 53.2,-85.6 61.1,-85.6 61.1,-66
  Top Layer region: -53.1,-66 -53.1,-58.1 -53.1,-58.1 -61,-58.1 -88.6,-58.1 -88.6,-66 -61,-66 -61,-85.6 -53.1,-85.6 -53.1,-66
  Top Layer region: 59.1,67.9 59.1,87.6 51.2,87.6 51.2,67.9 51.2,60 88.6,60 88.6,67.9
  Top Layer region: -51.2,67.9 -51.2,87.6 -59,87.6 -59,67.9 -88.6,67.9 -88.6,60 -51.1,60 -51.1,67.9
  silkscreen extent -108,-78 79,84
QFN-80_L10.0-W10.0-P0.40-TL-EP3.4 [mil]
  rect 26.2x8.7 smd: 1(-193.2,149.6) 2(-193.2,133.9) 3(-193.2,118.1) 4(-193.2,102.4) 5(-193.2,86.6) 6(-193.2,70.9) 7(-193.2,55.1) 8(-193.2,39.4) 9(-193.2,23.6) 10(-193.2,7.9) 11(-193.2,-7.9) 12(-193.2,-23.6) 13(-193.2,-39.4) 14(-193.2,-55.1) 15(-193.2,-70.9) 16(-193.2,-86.6) 17(-193.2,-102.4) 18(-193.2,-118.1) 19(-193.2,-133.9) 20(-193.2,-149.6) 41(193.2,-149.6) 42(193.2,-133.9) 43(193.2,-118.1) 44(193.2,-102.4) 45(193.2,-86.6) 46(193.2,-70.9) 47(193.2,-55.1) 48(193.2,-39.4) 49(193.2,-23.6) 50(193.2,-7.9) 51(193.2,7.9) 52(193.2,23.6) 53(193.2,39.4) 54(193.2,55.1) 55(193.2,70.9) 56(193.2,86.6) 57(193.2,102.4) 58(193.2,118.1) 59(193.2,133.9) 60(193.2,149.6)
  rect 8.7x26.2 smd: 21(-149.6,-193.2) 22(-133.8,-193.2) 23(-118.1,-193.2) 24(-102.3,-193.2) 25(-86.6,-193.2) 26(-70.8,-193.2) 27(-55.1,-193.2) 28(-39.3,-193.2) 29(-23.6,-193.2) 30(-7.8,-193.2) 31(7.9,-193.2) 32(23.7,-193.2) 33(39.4,-193.2) 34(55.2,-193.2) 35(70.9,-193.2) 36(86.6,-193.2) 37(102.4,-193.2) 38(118.1,-193.2) 39(133.9,-193.2) 40(149.6,-193.2) 61(149.6,193.2) 62(133.9,193.2) 63(118.1,193.2) 64(102.4,193.2) 65(86.6,193.2) 66(70.9,193.2) 67(55.2,193.2) 68(39.4,193.2) 69(23.7,193.2) 70(7.9,193.2) 71(-7.8,193.2) 72(-23.6,193.2) 73(-39.3,193.2) 74(-55.1,193.2) 75(-70.8,193.2) 76(-86.6,193.2) 77(-102.3,193.2) 78(-118.1,193.2) 79(-133.8,193.2) 80(-149.6,193.2)
  rect 133.9x133.9 smd: 81(0,0)
  silkscreen extent -215,-200 200,200
R0402#1 [mil]
  rect 22.3x21.3 smd paste-3937 mask+2: 1(-17,0) 2(17,0)
  silkscreen extent -37,-20 37,20
R0402#2 [mil]
  rect 22.3x21.3 smd paste-3937 mask+2: 1(-17.1,0) 2(17,0)
  silkscreen extent -37,-20 37,20
R0402#3 [mil]
  rect 22.3x21.3 smd paste-3937 mask+2: 1(-17,0) 2(17.1,0)
  silkscreen extent -37,-20 37,20
R0603#1 [mil]
  rect 31.8x34 smd paste-3937 mask+2: 1(-29.6,0) 2(29.7,0)
  silkscreen extent -54,-26 55,26
R0603#2 [mil]
  rect 31.8x34 smd paste-3937 mask+2: 1(-29.7,0) 2(29.7,0)
  silkscreen extent -54,-26 54,26
SOD-123_L2.7-W1.6-LS3.7-RD [mil]
  rect 35.8x48 smd: 1(-64.4,0) 2(64.4,0)
  silkscreen extent -63,-39 54,40
SOIC-8_L5.3-W5.3-P1.27-LS8.0-BL [mil]
  oval 24.8x88.6 smd: 1(-75,-139) 2(-25,-139) 3(25,-139) 4(75,-139) 5(75,139) 6(25,139) 7(-25,139) 8(-75,139)
  silkscreen extent -111,-145 104,86
SOIC-18_L11.6-W7.5-P1.27-LS10.3-BL [mil]
  oval 22x82.7 smd: 1(-200,-188.9) 2(-150,-188.9) 3(-100,-188.9) 4(-50,-188.9) 5(0,-188.9) 6(50,-188.9) 7(100,-188.9) 8(150,-188.9) 9(200,-188.9) 10(200,189) 11(150,189) 12(100,189) 13(50,189) 14(0,189) 15(-50,189) 16(-100,189) 17(-150,189) 18(-200,189)
  silkscreen extent -230,-135 230,135
SOT-23-3_L2.9-W1.3-P1.90-LS2.4-BR#1 [mil]
  rect 39.4x25.6 smd: 1(39.3,-37.4) 2(39.3,37.4) 3(-39.4,0)
  silkscreen extent -29,-60 29,60
SOT-23-3_L2.9-W1.3-P1.90-LS2.4-BR#2 [mil]
  rect 39.4x25.6 smd: 1(39.4,-37.4) 2(39.4,37.4) 3(-39.4,0)
  silkscreen extent -29,-60 29,60
SOT-23-6_L2.9-W1.6-P0.95-LS2.8-BL [mil]
  rect 20.9x42.2 smd: 1(-37.4,-45.3) 2(0,-45.3) 3(37.4,-45.3) 4(37.4,45.2) 5(0,45.2) 6(-37.4,45.2)
  silkscreen extent -72,-57 61,35
SOT-23-6_L2.9-W1.6-P0.95-LS2.8-BR [mil]
  rect 43.3x23.6 smd paste+0 mask+2: 1(53.2,-37.4) 2(53.2,0) 3(53.2,37.4) 4(-53.1,37.4) 5(-53.1,0) 6(-53.1,-37.4)
  silkscreen extent -35,-70 60,61
SW-SMD_4P-L6.5-W6.0-P4.00-LS6.6-TL [mil]
  rect 126x39.4 smd paste+0 mask+2: 1(-133.9,78.8) 2(133.9,78.8) 3(-133.9,-78.7) 4(133.9,-78.7)
  silkscreen extent -128,-120 128,118
TF-SMD_TF-01A [mil]
  rect 23.6x51.2 smd: 1(88.2,207.7) 2(44.9,207.7) 3(1.6,207.7) 4(-41.8,207.7) 5(-85.1,207.7) 6(-128.4,207.7) 7(-171.7,207.7) 8(-215,207.7) 9(-258.3,207.7)
  rect 47.2x55.1 smd: 10(-305.5,174.2) 13(272.4,174.2)
  rect 47.2x78.7 smd: 11(-305.5,-207.8) 12(305.5,-207.8)
  Board Outline Layer lines w0.1: -194.9,-199.5 -198.7,-199.9 -202.4,-201 -205.8,-202.8 -208.8,-205.3 -211.3,-208.2 -213.1,-211.6 -214.2,-215.3 -214.6,-219.2 -214.2,-223 -213.1,-226.7 -211.3,-230.1 -208.8,-233.1 -205.8,-235.5 -202.4,-237.4 -198.7,-238.5 -194.9,-238.9 -191.1,-238.5 -187.4,-237.4 -184,-235.5 -181,-233.1 -178.5,-230.1 -176.7,-226.7 -175.6,-223 -175.2,-219.2 -175.6,-215.3 -176.7,-211.6 -178.5,-208.2 -181,-205.3 -184,-202.8 -187.4,-201 -191.1,-199.9 -194.9,-199.5 ; 120.1,-199.5 116.2,-199.9 112.5,-201 109.1,-202.8 106.1,-205.3 103.7,-208.2 101.9,-211.6 100.8,-215.3 100.4,-219.2 100.8,-223 101.9,-226.7 103.7,-230.1 106.1,-233.1 109.1,-235.5 112.5,-237.4 116.2,-238.5 120.1,-238.9 123.9,-238.5 127.6,-237.4 131,-235.5 134,-233.1 136.4,-230.1 138.2,-226.7 139.4,-223 139.7,-219.2 139.4,-215.3 138.2,-211.6 136.4,-208.2 134,-205.3 131,-202.8 127.6,-201 123.9,-199.9 120.1,-199.5
  Board Outline Layer region: -175.2,-219.2 -175.6,-223 -176.7,-226.7 -178.5,-230.1 -181,-233.1 -184,-235.5 -187.4,-237.4 -191.1,-238.5 -194.9,-238.9 -198.7,-238.5 -202.4,-237.4 -205.8,-235.5 -208.8,-233.1 -211.3,-230.1 -213.1,-226.7 -214.2,-223 -214.6,-219.2 -214.2,-215.3 -213.1,-211.6 -211.3,-208.2 -208.8,-205.3 -205.8,-202.8 -202.4,-201 -198.7,-199.9 -194.9,-199.5 -191.1,-199.9 -187.4,-201 -184,-202.8 -181,-205.3 -178.5,-208.2 -176.7,-211.6 -175.6,-215.3
  Board Outline Layer region: -175.2,-219.2 -175.6,-223 -176.7,-226.7 -178.5,-230.1 -181,-233.1 -184,-235.5 -187.4,-237.4 -191.1,-238.5 -194.9,-238.9 -198.7,-238.5 -202.4,-237.4 -205.8,-235.5 -208.8,-233.1 -211.3,-230.1 -213.1,-226.7 -214.2,-223 -214.6,-219.2 -214.2,-215.3 -213.1,-211.6 -211.3,-208.2 -208.8,-205.3 -205.8,-202.8 -202.4,-201 -198.7,-199.9 -194.9,-199.5 -191.1,-199.9 -187.4,-201 -184,-202.8 -181,-205.3 -178.5,-208.2 -176.7,-211.6 -175.6,-215.3
  Board Outline Layer region: 139.7,-219.2 139.4,-223 138.2,-226.7 136.4,-230.1 134,-233.1 131,-235.5 127.6,-237.4 123.9,-238.5 120.1,-238.9 116.2,-238.5 112.5,-237.4 109.1,-235.5 106.1,-233.1 103.7,-230.1 101.9,-226.7 100.8,-223 100.4,-219.2 100.8,-215.3 101.9,-211.6 103.7,-208.2 106.1,-205.3 109.1,-202.8 112.5,-201 116.2,-199.9 120.1,-199.5 123.9,-199.9 127.6,-201 131,-202.8 134,-205.3 136.4,-208.2 138.2,-211.6 139.4,-215.3
  Board Outline Layer region: 139.7,-219.2 139.4,-223 138.2,-226.7 136.4,-230.1 134,-233.1 131,-235.5 127.6,-237.4 123.9,-238.5 120.1,-238.9 116.2,-238.5 112.5,-237.4 109.1,-235.5 106.1,-233.1 103.7,-230.1 101.9,-226.7 100.8,-223 100.4,-219.2 100.8,-215.3 101.9,-211.6 103.7,-208.2 106.1,-205.3 109.1,-202.8 112.5,-201 116.2,-199.9 120.1,-199.5 123.9,-199.9 127.6,-201 131,-202.8 134,-205.3 136.4,-208.2 138.2,-211.6 139.4,-215.3
  Multi-Layer board cut-out: -175.2,-219.2 -175.6,-223 -176.7,-226.7 -178.5,-230.1 -181,-233.1 -184,-235.5 -187.4,-237.4 -191.1,-238.5 -194.9,-238.9 -198.7,-238.5 -202.4,-237.4 -205.8,-235.5 -208.8,-233.1 -211.3,-230.1 -213.1,-226.7 -214.2,-223 -214.6,-219.2 -214.2,-215.3 -213.1,-211.6 -211.3,-208.2 -208.8,-205.3 -205.8,-202.8 -202.4,-201 -198.7,-199.9 -194.9,-199.5 -191.1,-199.9 -187.4,-201 -184,-202.8 -181,-205.3 -178.5,-208.2 -176.7,-211.6 -175.6,-215.3
  Multi-Layer board cut-out: 139.7,-219.2 139.4,-223 138.2,-226.7 136.4,-230.1 134,-233.1 131,-235.5 127.6,-237.4 123.9,-238.5 120.1,-238.9 116.2,-238.5 112.5,-237.4 109.1,-235.5 106.1,-233.1 103.7,-230.1 101.9,-226.7 100.8,-223 100.4,-219.2 100.8,-215.3 101.9,-211.6 103.7,-208.2 106.1,-205.3 109.1,-202.8 112.5,-201 116.2,-199.9 120.1,-199.5 123.9,-199.9 127.6,-201 131,-202.8 134,-205.3 136.4,-208.2 138.2,-211.6 139.4,-215.3
  silkscreen extent -290,-377 290,134
USB-C_SMD-TYPE-C-31-M-12_1 [mil]
  oval 47.2x78.7 hole 31.5 slot 59.1 at 90 deg paste+0 mask+2: 1(170.3,67.1) 4(-170.3,67.1)
  oval 47.2x70.9 hole 31.5 slot 47.2 at 90 deg paste+0 mask+2: 2(170.3,-97.4) 3(-170.3,-97.4)
  round 11.8 smd: A1B12(-126,97.4) A4B9(-94.5,97.4)
  rect 11.8x51.2 smd paste-3937 mask+2: A5(-49.2,97.4) A6(-9.8,97.4) A7(9.8,97.4) A8(49.2,97.4) B5(68.9,97.4) B6(29.5,97.4) B7(-29.5,97.4) B8(-68.9,97.4)
  rect 23.6x51.2 smd paste-3937 mask+2: B1A12(126,97.4) B4A9(94.5,97.4)
  Top Layer region: -114.2,71.8 -114.2,123 -126,123 -126,123 -137.8,123 -137.8,71.8 -126,71.8 -126,71.8
  Top Layer region: -82.7,71.8 -82.7,123 -94.5,123 -94.5,123 -106.3,123 -106.3,71.8 -94.5,71.8 -94.5,71.8
  Board Outline Layer lines w0.1: 126,47.4 125.6,44.5 124.5,41.7 122.8,39.3 120.5,37.5 117.8,36.2 114.9,35.6 112,35.8 109.1,36.7 106.6,38.3 104.6,40.5 103.2,43.1 102.4,46 102.4,48.9 103.2,51.8 104.6,54.4 106.6,56.5 109.1,58.1 112,59 114.9,59.2 117.8,58.7 120.5,57.4 122.8,55.5 124.5,53.1 125.6,50.4 126,47.4 ; -102.4,47.4 -102.7,44.5 -103.8,41.7 -105.6,39.3 -107.8,37.5 -110.5,36.2 -113.4,35.6 -116.4,35.8 -119.2,36.7 -121.7,38.3 -123.7,40.5 -125.2,43.1 -125.9,46 -125.9,48.9 -125.2,51.8 -123.7,54.4 -121.7,56.5 -119.2,58.1 -116.4,59 -113.4,59.2 -110.5,58.7 -107.8,57.4 -105.6,55.5 -103.8,53.1 -102.7,50.4 -102.4,47.4
  Board Outline Layer region: -102.4,47.4 -102.7,44.5 -103.8,41.7 -105.6,39.3 -107.8,37.5 -110.5,36.2 -113.4,35.6 -116.4,35.8 -119.2,36.7 -121.7,38.3 -123.7,40.5 -125.2,43.1 -125.9,46 -125.9,48.9 -125.2,51.8 -123.7,54.4 -121.7,56.5 -119.2,58.1 -116.4,59 -113.4,59.2 -110.5,58.7 -107.8,57.4 -105.6,55.5 -103.8,53.1 -102.7,50.4
  Board Outline Layer region: -102.4,47.4 -102.7,44.5 -103.8,41.7 -105.6,39.3 -107.8,37.5 -110.5,36.2 -113.4,35.6 -116.4,35.8 -119.2,36.7 -121.7,38.3 -123.7,40.5 -125.2,43.1 -125.9,46 -125.9,48.9 -125.2,51.8 -123.7,54.4 -121.7,56.5 -119.2,58.1 -116.4,59 -113.4,59.2 -110.5,58.7 -107.8,57.4 -105.6,55.5 -103.8,53.1 -102.7,50.4
  Board Outline Layer region: 126,47.4 125.6,44.5 124.5,41.7 122.8,39.3 120.5,37.5 117.8,36.2 114.9,35.6 112,35.8 109.1,36.7 106.6,38.3 104.6,40.5 103.2,43.1 102.4,46 102.4,48.9 103.2,51.8 104.6,54.4 106.6,56.5 109.1,58.1 112,59 114.9,59.2 117.8,58.7 120.5,57.4 122.8,55.5 124.5,53.1 125.6,50.4
  Board Outline Layer region: 126,47.4 125.6,44.5 124.5,41.7 122.8,39.3 120.5,37.5 117.8,36.2 114.9,35.6 112,35.8 109.1,36.7 106.6,38.3 104.6,40.5 103.2,43.1 102.4,46 102.4,48.9 103.2,51.8 104.6,54.4 106.6,56.5 109.1,58.1 112,59 114.9,59.2 117.8,58.7 120.5,57.4 122.8,55.5 124.5,53.1 125.6,50.4
  Multi-Layer board cut-out: -102.4,47.4 -102.7,44.5 -103.8,41.7 -105.6,39.3 -107.8,37.5 -110.5,36.2 -113.4,35.6 -116.4,35.8 -119.2,36.7 -121.7,38.3 -123.7,40.5 -125.2,43.1 -125.9,46 -125.9,48.9 -125.2,51.8 -123.7,54.4 -121.7,56.5 -119.2,58.1 -116.4,59 -113.4,59.2 -110.5,58.7 -107.8,57.4 -105.6,55.5 -103.8,53.1 -102.7,50.4
  Multi-Layer board cut-out: 126,47.4 125.6,44.5 124.5,41.7 122.8,39.3 120.5,37.5 117.8,36.2 114.9,35.6 112,35.8 109.1,36.7 106.6,38.3 104.6,40.5 103.2,43.1 102.4,46 102.4,48.9 103.2,51.8 104.6,54.4 106.6,56.5 109.1,58.1 112,59 114.9,59.2 117.8,58.7 120.5,57.4 122.8,55.5 124.5,53.1 125.6,50.4
  silkscreen extent -176,-201 176,19
USON-8_L3.0-W2.0-P0.50-BL-EP [mil]
  rect 11x23.6 smd: 1(-29.5,-59.4) 2(-9.8,-59.4) 3(9.8,-59.4) 4(29.5,-59.4) 5(29.5,59.3) 6(9.8,59.3) 7(-9.8,59.3) 8(-29.5,59.3)
  rect 66.9x11.8 smd: 9(0,0)
  silkscreen extent -42,-84 42,62

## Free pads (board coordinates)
  round 122 hole 118.1: 1(3424.1,5772.9) 2(6144.1,5777.9) 3(6139.1,3917.9) 4(3414.1,3922.9)

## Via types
v1: diameter 24, hole 12, Top Layer to Bottom Layer, tented both sides, 260 vias

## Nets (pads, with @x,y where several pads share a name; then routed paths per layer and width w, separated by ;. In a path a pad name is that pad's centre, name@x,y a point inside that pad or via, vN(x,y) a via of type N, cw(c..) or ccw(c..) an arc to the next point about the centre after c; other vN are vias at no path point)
$1N5: R17.1 U1.35 U16.1 | length 1407.2
  Top Layer w7.8: U1.35@4867.3,5213.8 4890.3,5213.8 4920.3,5243.8 4950.3,5243.8 4970.3,5263.8 5093.9,5263.8 R17.1@5095.5,5265.5
  Top Layer w10: 4980.3,5263.8 4970.3,5273.8 4970.3,5693.8 v1(5020.3,5743.8) ; v1(5060.3,6253.8) U16.1@5060.3,6371.6
  Inner1 w10: v1(5020.3,5743.8) 5010.3,5753.8 5010.3,6203.8 v1(5060.3,6253.8)
$1N58: U1.75 U6.1 | length 697.9
  Top Layer w7.8: v1(4293,4492.9) 4293,4465 U6.1@4295.1,4462.9 ; v1(4363.9,4802.1) 4363.9,4902.1 4413.9,4952.1 4413.9,5022.1 4463.9,5072.1 U1.75@4480.9,5072.1
  Inner1 w7.8: v1(4293,4492.9) 4293,4731.2 v1(4363.9,4802.1)
$1N61: U1.74 U6.2 U7.2 | length 1756.8
  Top Layer w7.8: U6.2@4295.1,4412.9 4310.9,4412.9 4350.9,4452.9 4350.9,4529.4 v1(4343.8,4536.5) ; U7.2@4338.9,5797.3 4340.9,5795.3 v1(4340.9,5767.8) ; v1(4340.9,4977.8) 4340.9,5047.8 4380.9,5087.8 U1.74@4480.9,5087.8
  Inner2 w7.8: v1(4324.6,4507.6) 4343.8,4526.8 v1(4343.8,4536.5) ; v1(4340.9,4977.8) 4350.9,4987.8 4350.9,5757.8 v1(4340.9,5767.8)
  Bottom Layer w7.8: v1(4340.9,4977.8) 4340.9,4967.8 4300.9,4927.8 4300.9,4532.9 4340.3,4532.9 v1(4343.8,4536.5)
$1N63: U1.73 U6.3 U7.3 | length 1743.9
  Top Layer w7.8: v1(4245.1,4437.8) 4235.1,4427.8 4235.1,4407.8 4280,4362.9 U6.3@4295.1,4362.9 ; v1(4300.9,5063.6) 4360.9,5123.6 4380.9,5123.6 ; v1(4319.3,5255.2) 4319.3,5185.2 4400.9,5103.6 U1.73@4480.9,5103.6 ; U7.3@4319.3,5797.3 v1(4319.3,5823.1)
  Inner1 w7.8: v1(4245.1,4437.8) 4245.1,4707.8 4300.9,4763.6 4300.9,4913.6 4280.9,4933.6 4280.9,5043.6 v1(4300.9,5063.6)
  Inner2 w7.8: v1(4319.3,5255.2) 4317.2,5257.3 4317.2,5821 v1(4319.3,5823.1)
$1N65: U1.72 U6.5 U7.5 | length 1730
  Top Layer w7.8: v1(4290.9,5409.3) 4290.9,5669.9 U7.5@4299.6,5678.6 ; v1(4400.9,5139.3) 4420.9,5119.3 U1.72@4480.9,5119.3 ; v1(4420.9,4609.3) 4420.9,4449.3 4550.9,4319.3 4566.7,4319.3 U6.5@4573.1,4312.9
  Inner1 w7.8: v1(4300.9,5099.3) 4370.9,5029.3 4370.9,4879.3 4400.9,4849.3 4400.9,4629.3 v1(4420.9,4609.3)
  Bottom Layer w7.8: v1(4290.9,5409.3) 4290.9,5249.3 v1(4400.9,5139.3) ; v1(4300.9,5099.3) 4280.9,5119.3 4280.9,5169.3 4320.9,5209.3 4330.9,5209.3
$1N67: U1.71 U6.6 U7.6 | length 1555.7
  Top Layer w7.8: U7.6@4319.3,5678.6 4319.3,5286.7 4350.9,5255.1 4350.9,5225.1 4390.9,5185.1 4400.9,5185.1 4450.9,5135.1 U1.71@4480.9,5135.1 ; v1(4400.9,5175.1) v1@4410.9,5175.1 ; v1(4480.9,4495.1) 4480.9,4435.1 4550.9,4365.1 4571,4365.1 U6.6@4573.1,4362.9
  Inner1 w7.8: v1(4400.9,5175.1) 4470.9,5105.1 4470.9,4995.1 4450.9,4975.1 v1(4450.9,4775.1)
  Bottom Layer w7.8: v1(4450.9,4775.1) 4480.9,4745.1 v1(4480.9,4495.1)
$1N69: U1.70 U6.7 U7.7 | length 1603.9
  Top Layer w7.8: U7.7@4338.9,5678.6 4338.9,5610.7 4373.9,5575.8 4373.9,5240.8 4463.9,5150.8 U1.70@4480.9,5150.8 4460.9,5150.8 v1(4400.9,5210.8) ; v1(4450.9,4610.8) 4510.9,4550.8 4510.9,4460.8 4558.8,4412.9 U6.7@4573.1,4412.9
  Inner1 w7.8: v1(4400.9,5210.8) 4370.9,5180.8 4370.9,5130.8 4420.9,5080.8 4420.9,4640.8 v1(4450.9,4610.8)
$1N76: U1.66 U2.4 U3.7 USBC1.A7 | length 3133.7
  Top Layer w7.1: U3.7@5404.6,4221.2 5404.6,4207.4 5420.9,4191.2 5444.6,4191.2 v1(5460.9,4207.4)
  Top Layer w7.8: U1.66@4480.9,5213.8 4500.9,5213.8 4510.9,5203.8 v1(4520.9,5203.8) ; v1(4680.9,6143.8) 4694.3,6157.2 USBC1.A7@4694.3,6215.5 ; v1(5370.9,5083.8) 5410.9,5083.8 5430.9,5063.8 5430.9,5044.9 U2.4@5434.7,5041
  Inner1 w7.1: v1(5370.9,5083.8) 5390.9,5063.8 5390.9,4313.8 5460.9,4243.8 v1(5460.9,4207.4)
  Inner2 w7.8: v1(4520.9,5203.8) 4520.9,5363.8 4620.9,5463.8 4620.9,5543.8 4600.9,5563.8 4600.9,6063.8 v1(4680.9,6143.8)
  Bottom Layer w7.8: v1(4520.9,5203.8) 4540.9,5203.8 4590.9,5153.8 5270.9,5153.8 5340.9,5083.8 v1(5370.9,5083.8)
$1N77: L1.1 U1.63 | length 917.6
  Top Layer w7.8: L1.1@4349.1,6087.8 4480.9,5956 v1(4480.9,5801.6) ; v1(4450.9,5311.6) 4450.9,5271.6 4460.9,5261.6 4480.3,5261.6 U1.63@4480.9,5261
  Bottom Layer w7.8: v1(4450.9,5311.6) 4480.9,5341.6 v1(4480.9,5801.6)
$1N84: H1.1 U1.77 | length 1125.3
  Top Layer w7.8: v1(4443.9,5020.6) 4463.9,5040.6 U1.77@4480.9,5040.6
  Inner2 w7.8: v1(4443.9,5020.6) 4493.9,5070.6 4493.9,5360.6 4553.9,5420.6 4553.9,6047.7 H1.1@4559.1,6052.9
$1N85: H1.2 U1.78 | length 1111.9
  Top Layer w7.8: U1.78@4480.9,5024.8 4497.9,5024.8 v1(4547.9,5074.8)
  Inner2 w7.8: v1(4547.9,5074.8) 4659.1,5186 H1.2@4659.1,6052.9
$1N86: H1.3 U1.79 | length 1719.8
  Top Layer w7.8: U1.79@4480.9,5009.1 v1(4517.9,5009.1)
  Inner1 w7.8: v1(4307.9,5159.1) 4307.9,5209.1 4427.9,5329.1 v1(4427.9,5559.1)
  Inner2 w7.8: v1(4427.9,5559.1) 4437.9,5569.1 4437.9,5809.1 4397.9,5849.1 4397.9,5989.1 4577.9,6169.1 4687.9,6169.1 4759.1,6097.8 H1.3@4759.1,6052.9
  Bottom Layer w7.8: v1(4307.9,5159.1) 4347.9,5159.1 4497.9,5009.1 v1(4517.9,5009.1)
$1N87: H1.4 U1.80 | length 1273.8
  Top Layer w7.8: v1(4480.9,4973.3) U1.80@4480.9,4993.3
  Inner1 w7.8: v1(4480.9,4973.3) 4490.9,4983.3 4490.9,5053.3 4680.9,5243.3 4680.9,5313.3 4710.9,5343.3 4740.9,5343.3 4850.9,5453.3 4850.9,6044.7 H1.4@4859.1,6052.9
$1N88: H1.5 U1.1 | length 1772.7
  Top Layer w7.8: v1(4394.5,4892.7) 4451.5,4949.7 U1.1@4524.5,4949.7
  Inner1 w7.8: v1(4394.5,4892.7) v1(4394.5,5062.7)
  Inner2 w7.8: v1(4394.5,5062.7) 4424.5,5092.7 4424.5,5510.2 4458.9,5544.6 4458.9,5902.7 v1(4448.9,5912.7)
  Bottom Layer w7.8: v1(4448.9,5912.7) 4818.9,5912.7 H1.5@4959.1,6052.9
$1N89: H1.6 U1.2 | length 1392.1
  Top Layer w7.8: U1.2@4540.2,4949.7 4540.2,4932.7 v1(4560.2,4912.7)
  Inner1 w7.8: v1(4560.2,4912.7) 4600.2,4952.7 4600.2,5032.7 5049.2,5481.7 5049.2,6043 H1.6@5059.1,6052.9
$1N90: H1.7 U1.3 | length 1459.3
  Top Layer w7.8: U1.3@4556,4949.7 4556,4979.7 v1(4566,4989.7)
  Inner2 w7.8: v1(4566,4989.7) 4566,4999.7 4676,5109.7 4676,5309.7 4726,5359.7 4766,5359.7 4826,5419.7 4826,5469.7 v1(4726,5569.7)
  Bottom Layer w7.8: v1(4726,5569.7) 5159.1,6002.8 H1.7@5159.1,6052.9
$1N91: H1.8 U1.4 | length 1761.2
  Top Layer w7.8: U1.4@4571.7,4949.7 4571.7,4932.7 v1(4591.7,4912.7)
  Bottom Layer w7.8: v1(4591.7,4912.7) 4591.7,5062.7 4551.7,5102.7 4511.7,5102.7 4421.7,5192.7 4421.7,5202.7 4551.7,5332.7 4551.7,5395.6 4701.7,5545.6 4701.7,5625.6 5111.7,6035.6 5111.7,6075.6 5131.7,6095.6 5216.5,6095.6 H1.8@5259.1,6052.9
$1N92: H1.9 U1.6 | length 1416.3
  Top Layer w7.8: U1.6@4603.2,4949.7 4603.2,4966.7 v1(4633.2,4996.7)
  Inner1 w7.8: v1(4633.2,4996.7) 5359.1,5722.6 H1.9@5359.1,6052.9
$1N93: H1.10 U1.7 | length 1662.7
  Top Layer w7.8: v1(4589,4882.7) 4599,4882.7 4619,4902.7 U1.7@4619,4949.7
  Inner1 w7.8: v1(4589,4882.7) 4599,4882.7 4669,4952.7 4669,4982.7 4869,5182.7 4939,5182.7 5459.1,5702.9 H1.10@5459.1,6052.9
$1N95: H1.12 U1.9 | length 1630.1
  Top Layer w7.8: U1.9@4650.5,4949.7 4650.5,4932.7 v1(4670.5,4912.7)
  Inner1 w7.8: v1(4670.5,4912.7) 4750.5,4992.7 4750.5,5032.7 4880.5,5162.7 4940.5,5162.7 5570.5,5792.7 v1(5570.5,5952.7)
  Bottom Layer w7.8: v1(5570.5,5952.7) 5570.5,5964.3 H1.12@5659.1,6052.9
$1N101: CARD1.5 U1.16 | length 1351.7
  Top Layer w7.8: U1.16@4760.7,4949.7 4761.4,4949 v1(4761.4,4887.1) ; v1(5765.6,4942.9) 5856.9,4942.9 5905,4894.8 ; 5906.9,4892.9 5905,4894.8 ; CARD1.5@5955.1,4894.8 5905,4894.8
  Inner1 w7.8: v1@4760.7,4893.6 4761.4,4892.9 v1(4761.4,4887.1)
  Bottom Layer w7.8: v1@4765.6,4882.9 v1(4761.4,4887.1) 4881.4,4887.1 4925.6,4842.9 5105.6,4842.9 5205.6,4942.9 v1(5765.6,4942.9)
$1N102: CARD1.2 U1.17 | length 1543.6
  Top Layer w7.8: U1.17@4776.5,4949.7 4776.5,4909.7 4803.4,4882.8 v1(4803.4,4812.8) ; v1(5835.6,5042.8) 5853.7,5024.7 ; 5855.6,5022.8 5853.7,5024.7 ; CARD1.2@5955.1,5024.7 5853.7,5024.7
  Inner1 w7.8: v1(4803.4,4812.8) 4803.4,4822.8 4877.7,4897.1 4912.4,4897.1 4978.1,4962.8 5145.6,4962.8 5385.6,5202.8 5455.6,5202.8 5615.6,5042.8 v1(5835.6,5042.8)
$1N103: CARD1.7 U1.18 | length 1376.7
  Top Layer w7.8: U1.18@4792.2,4949.7 4792.2,4969.7 4795.6,4973.1 4838.8,4973.1 4875.6,4936.3 v1(4875.6,4856.3) ; v1(5785.6,4916.3) 5893.7,4808.1 ; 5895.6,4806.3 5893.7,4808.1 ; CARD1.7@5955.1,4808.1 5893.7,4808.1
  Bottom Layer w7.8: v1(4875.6,4856.3) 4905.6,4826.3 5115.6,4826.3 5205.6,4916.3 v1(5785.6,4916.3)
$1N104: CARD1.1 U1.19 | length 1243.7
  Top Layer w7.8: U1.19@4808,4949.7 4809.2,4948.5 v1(4809.2,4909.7) ; v1(5765.6,5006.1) 5825.6,5066.1 CARD1.1@5947.6,5066.1
  Bottom Layer w7.8: v1(4809.2,4909.7) 5149.2,4909.7 5205.6,4966.1 5725.6,4966.1 v1(5765.6,5006.1)
$1N105: CARD1.9 R6.1 U1.20 | length 1974.2
  Top Layer w7.8: U1.20@4823.7,4949.7 4833.8,4939.7 v1(4833.8,4819.7)
  Top Layer w10: R6.1@5184.1,4160.8 5192.9,4169.7 v1(5294.5,4169.7) ; v1(5834.5,4699.7) 5854.5,4719.7 CARD1.9@5947.6,4719.7
  Bottom Layer w7.8: v1(4833.8,4819.7) 4853.8,4819.7 4883.8,4789.7 5003.8,4789.7 5454.5,4338.9 5454.5,4319.7
  Bottom Layer w10: v1(5294.5,4169.7) 5374.5,4249.7 5374.5,4259.7 5394.5,4279.7 5414.5,4279.7 v1(5834.5,4699.7)
$1N107: U1.22 U23.1 | length 1420.5
  Top Layer w7.8: U1.22@4867.3,5009.1 4894.3,5009.1 v1(4904.3,4999.1)
  Inner1 w7.8: U23.1@3894.1,4164.5 4069.7,4164.5 4784.3,4879.1 4784.3,4919.1 4864.3,4999.1 v1(4904.3,4999.1)
$1N110: U1.21 U19.1 | length 973.1
  Top Layer w7.8: U1.21@4867.3,4993.3 4927.3,4933.3 v1(4927.3,4873.3)
  Inner2 w7.8: U19.1@4779.1,4106.4 4779.1,4315.1 4897.3,4433.3 4897.3,4843.3 v1(4927.3,4873.3)
$1N118: U1.23 U24.1 | length 1663.8
  Top Layer w7.8: v1(4780.3,4994.8) 4810.3,4994.8 4840.3,5024.8 U1.23@4867.3,5024.8
  Inner2 w7.8: U24.1@3609.1,4164.5 4099.4,4654.8 4410.3,4654.8 v1(4620.3,4864.8)
  Bottom Layer w7.8: v1(4620.3,4864.8) 4620.3,4934.8 4690.3,5004.8 4770.3,5004.8 v1(4780.3,4994.8)
$1N119: U1.25 U25.1 | length 1821.1
  Top Layer w7.8: v1(4810.3,5026.3) 4840.3,5056.3 U1.25@4867.3,5056.3
  Inner2 w7.8: U25.1@3205.7,4727.9 3254.1,4776.3 4390.3,4776.3 4550.3,4936.3 4760.3,4936.3 4810.3,4986.3 v1(4810.3,5026.3)
$1N120: U1.26 U26.1 | length 1715.3
  Top Layer w7.8: U1.26@4867.3,5072.1 v1(4904.3,5072.1)
  Inner2 w7.8: U26.1@4254.1,4101.4 4293.4,4062.1 4794.3,4062.1 4824.3,4092.1 4824.3,4282.1 4954.3,4412.1 4954.3,4832.1 4984.3,4862.1 4984.3,4982.1 4904.3,5062.1 v1(4904.3,5072.1)
$1N122: U1.28 U28.1 | length 1927.7
  Top Layer w7.8: U1.28@4867.3,5103.6 4904.3,5103.6 4934.3,5073.6 v1(4934.3,5063.6)
  Inner1 w7.8: U28.1@3729.1,3724.5 3774.3,3769.7 3774.3,3833.6 4934.3,4993.6 v1(4934.3,5063.6)
$1N124: U1.27 U27.1 | length 1779.6
  Top Layer w7.8: v1(4780.3,5027.8) 4840.3,5087.8 U1.27@4867.3,5087.8
  Inner2 w7.8: U27.1@3205.7,4982.9 3255.7,5032.9 3415.5,5032.9 3475.5,4972.9 3960.5,4972.9 3990.5,4942.9 4485.4,4942.9 4505.4,4962.9 4635.4,4962.9 4700.3,5027.8 v1(4780.3,5027.8)
$1N128: U1.36 U29.1 | length 1554.3
  Top Layer w7.8: v1(4830.3,5229.5) U1.36@4867.3,5229.5
  Inner1 w7.8: v1(4650.3,5049.5) v1(4830.3,5229.5)
  Inner2 w7.8: U29.1@4519.1,4106.4 4519.1,4608.3 4784.3,4873.6 4784.3,4933.6 4840.3,4989.5 4840.3,5029.5 4810.3,5059.5 4660.3,5059.5 v1(4650.3,5049.5)
$1N129: U1.37 U30.1 | length 2287.3
  Top Layer w7.8: v1(4850.3,5315.3) 4840.3,5305.3 4840.3,5255.3 4850.3,5245.3 U1.37@4867.3,5245.3
  Inner1 w7.8: U30.1@3334.1,4164.5 3384.9,4215.3 4090.3,4215.3 4480.3,4605.3 4480.3,4935.3 4850.3,5305.3 v1(4850.3,5315.3)
$1N130: U1.38 U20.1 | length 1566.2
  Top Layer w7.8: U1.38@4867.3,5261 4934.3,5261 v1(4944.3,5271)
  Inner2 w7.8: v1(6014.3,5491) 6162.2,5491 U20.1@6269.1,5597.9
  Bottom Layer w7.8: v1(4944.3,5271) 4974.3,5241 5144.3,5241 5324.3,5421 5794.3,5421 5864.3,5491 v1(6014.3,5491)
$1N131: U1.39 U20.2 | length 1670.9
  Top Layer w7.8: U1.39@4867.3,5276.8 4915.8,5276.8 4954.3,5315.3 4954.3,5586.8 v1(4944.3,5596.8)
  Bottom Layer w7.8: v1(4944.3,5596.8) 5724.3,5596.8 5744.3,5616.8 5884.3,5616.8 5953.2,5547.9 6119.1,5547.9 U20.2@6169.1,5597.9
$1N132: R9.1 U1.40 | length 329.2
  Top Layer w7.8: U1.40@4867.3,5292.5 4897.3,5292.5 v1(4927.3,5322.5) ; v1(5134.4,5265.5) R9.1@5160.5,5265.5
  Bottom Layer w7.8: v1(4927.3,5322.5) 4984.4,5265.5 v1(5134.4,5265.5)
$1N133: LED1.2 R9.2 | length 611.4
  Top Layer w10: LED1.2@4984.6,4692.9 4984.6,4732.9 v1(5004.6,4752.9) ; v1(5144.6,4992.9) 5144.6,5215.5 R9.2@5160.5,5231.4
  Inner2 w10: v1(5004.6,4752.9) 5004.6,4832.9 5144.6,4972.9 v1(5144.6,4992.9)
$1N134: U1.42 U7.1 | length 807.9
  Top Layer w7.8: U7.1@4358.6,5797.3 4414.5,5853.1 v1(4428,5853.1) ; v1(4798,5433.1) 4808,5423.1 U1.42@4808,5336.1
  Inner1 w7.8: v1(4428,5853.1) 4448,5833.1 4518,5833.1 v1(4688,5663.1)
  Inner2 w7.8: v1(4688,5663.1) 4688,5543.1 v1(4798,5433.1)
$1N135: C1.1 U1.68 | length 1014
  Top Layer w7.8: U1.68@4480.9,5182.3 4510.9,5182.3 4520.9,5172.3 v1(4540.9,5172.3) ; v1(4630.9,5572.3) 4833,5774.4 C1.1@5051.5,5774.4
  Inner2 w7.8: v1(4540.9,5172.3) 4590.9,5222.3 4590.9,5362.3 4640.9,5412.3 4640.9,5562.3 v1(4630.9,5572.3)
$1N136: U1.43 U18.24 | length 1394.7
  Top Layer w7.8: v1(3734.9,5973.4) U18.24@3767.3,5973.4 ; v1(4692.2,5456.1) 4712.2,5456.1 4792.2,5376.1 U1.43@4792.2,5336.1
  Inner1 w7.8: v1(3734.9,5973.4) 4204.9,5973.4 4342.2,5836.1 4342.2,5826.1 4692.2,5476.1 v1(4692.2,5456.1)
$1N137: U1.44 U17.2 U18.57 | length 2729.1
  Top Layer w7.8: v1(4116.5,5833.1) 4096.5,5813.1 4096.5,5793.1 4113,5776.6 U18.57@4151.6,5776.6 ; v1(4586.5,5483.1) 4626.5,5483.1 4676.5,5433.1 4706.5,5433.1 4776.5,5363.1 U1.44@4776.5,5336.1 ; 4656.5,5453.1 4686.5,5483.1 v1(4716.5,5483.1) ; v1(5696.5,4753.1) 5696.5,4722.8 U17.2@5715.6,4703.6
  Inner1 w7.8: v1(4116.5,5833.1) 4126.5,5823.1 4186.5,5823.1 4236.5,5773.1 4286.5,5773.1 4576.5,5483.1 v1(4586.5,5483.1)
  Inner2 w7.8: v1(5376.5,5543.1) 5696.5,5223.1 v1(5696.5,4753.1)
  Bottom Layer w7.8: v1(4716.5,5483.1) 4776.5,5543.1 v1(5376.5,5543.1)
$1N138: U1.45 U18.58 | length 1496.2
  Top Layer w7.8: v1(4121.6,5800) 4147.9,5800 U18.58@4151.6,5796.3 ; U1.45@4760.7,5336.1 4760.7,5309.1 v1(4770.7,5299.1)
  Inner1 w7.8: v1(4770.7,5299.1) 4770.7,5349.1 4877.8,5456.3 v1(4877.8,5886.3)
  Bottom Layer w7.8: v1(4121.6,5800) 4207.9,5886.3 v1(4877.8,5886.3)
$1N139: U1.46 U17.3 U18.59 | length 2538.6
  Top Layer w7.8: U18.59@4151.6,5816 4154.4,5813.1 v1(4265,5813.1) ; v1(4725,5383.1) 4725,5373.1 4745,5353.1 U1.46@4745,5336.1 ; v1(5750.7,4703.1) 5750.7,4683.1 5760.7,4673.1 5780.7,4673.1 U17.3@5782.6,4671.3
  Inner1 w7.8: v1(4265,5813.1) 4285,5793.1 4355,5793.1 4605,5543.1 4605,5503.1 v1(4725,5383.1)
  Inner2 w7.8: v1(5345,5493.1) 5345,5393.1 5665,5073.1 5665,4753.1 5715,4703.1 v1(5750.7,4703.1)
  Bottom Layer w7.8: v1(4725,5383.1) 4725,5393.1 4825,5493.1 v1(5345,5493.1)
$1N142: U1.48 U15.14 | length 1062.3
  Top Layer w7.8: U15.14@3910.2,4899.5 3913.9,4903.1 3913.9,4913.1 3933.9,4933.1 v1(3953.5,4933.1) ; v1(4693.5,5383.1) 4713.5,5363.1 U1.48@4713.5,5336.1
  Inner1 w7.8: v1(3953.5,4933.1) 4143.5,5123.1 4303.5,5123.1 4333.5,5153.1 4333.5,5183.1 4383.5,5233.1 4513.5,5233.1 4603.5,5323.1 4633.5,5323.1 v1(4693.5,5383.1)
$1N144: U1.53 U2.10 | length 1587.6
  Top Layer w7.8: U1.53@4634.7,5336.1 v1(4634.7,5366.1) ; v1(5504.7,4992.9) 5524.7,4992.9 5564.7,4952.9 5564.7,4816.7 U2.10@5552.8,4804.8
  Bottom Layer w7.8: v1(4634.7,5366.1) 4494.7,5226.1 4494.7,5186.1 4544.7,5136.1 5194.7,5136.1 5337.9,4992.9 v1(5504.7,4992.9)
$1N152: U1.54 U31.1 | length 1247
  Top Layer w7.8: v1(4619,5299.1) U1.54@4619,5336.1
  Bottom Layer w7.8: v1(4619,5299.1) 4679,5359.1 4759,5359.1 4867.8,5467.9 U31.1@5759.1,5467.9
$1N156: U1.56 U32.1 | length 1910.7
  Top Layer w7.8: U1.56@4587.5,5336.1 4587.5,5299.1 v1(4617.5,5269.1)
  Bottom Layer w7.8: v1(4617.5,5269.1) 4597.5,5249.1 4597.5,5229.1 4647.5,5179.1 5147.5,5179.1 5317.5,5349.1 6220.3,5349.1 U32.1@6269.1,5397.9
$1N157: U1.57 U32.2 | length 1744.3
  Top Layer w7.8: U1.57@4571.7,5336.1 4571.7,5376.1 v1(4581.7,5386.1)
  Bottom Layer w7.8: v1(4581.7,5386.1) 4611.7,5386.1 4631.7,5406.1 4711.7,5406.1 4821.7,5516.1 6050.9,5516.1 U32.2@6169.1,5397.9
$1N158: U1.58 U32.3 | length 1716.3
  Top Layer w7.8: U1.58@4556,5336.1 4556,5299.1 4616,5239.1 v1(4626,5239.1)
  Bottom Layer w7.8: v1(4626,5239.1) 4646,5259.1 4924.8,5259.1 4964.8,5219.1 5146,5219.1 5316,5389.1 5896,5389.1 5956,5449.1 6017.9,5449.1 U32.3@6069.1,5397.9
$1N165: C5.1 U18.21 X2.4 | length 1785.3
  Top Layer w8.1: X2.4@3680.6,5304.6 3640.6,5344.6 3640.6,5955.6 3717.5,6032.5 U18.21@3767.3,6032.5
  Top Layer w10: X2.4@3680.6,5304.6 3790.6,5194.6 3870.6,5194.6 4010.6,5054.6 4194,5054.6 4254,4994.6 4254,4864.6 C5.1@4344.1,4774.5
$1N166: C4.1 U18.22 X2.2 | length 2600.1
  Top Layer w8.1: X2.2@3747.6,5391.2 3697.5,5441.3 3697.5,5972.8 3737.5,6012.8 U18.22@3767.3,6012.8
  Top Layer w10: v1(5257.5,5212.8) 5295.8,5212.8 C4.1@5307,5224
  Inner1 w10: v1(3727.5,6002.8) 4237.5,6002.8 4647.5,5592.8 v1(4827.5,5592.8)
  Inner2 w10: v1(4827.5,5592.8) 4877.5,5592.8 v1(5257.5,5212.8)
$1N185: U1.47 U14.11 | length 1102.8
  Top Layer w7.8: U1.47@4729.2,5336.1 4729.2,5319.1 4739.2,5309.1 v1(4739.2,5289.1) ; U14.11@4873.7,4438.1 4873.7,4458.1 4889.2,4473.6 v1(4919.2,4473.6)
  Inner1 w7.8: v1(4919.2,4473.6) 4979.2,4533.6 v1(4979.2,4543.6)
  Inner2 w7.8: v1(4739.2,5289.1) 4939.2,5089.1 4979.2,5089.1 4999.2,5069.1 4999.2,4849.2 4979.2,4829.2 v1(4979.2,4543.6)
$1N190: U1.52 U3.21 | length 1326.9
  Top Layer w7.1: U1.52@4650.5,5336.1 4650.5,5299.5 v1(4720.5,5229.5) ; v1(5330.5,4409.5) 5340.5,4409.5 5357.4,4392.6 U3.21@5357.4,4374.7
  Inner2 w7.1: v1(4720.5,5229.5) 4860.5,5089.5 4860.5,4939.5 4850.5,4929.5 4850.5,4849.5 4870.5,4829.5 v1(4870.5,4769.5)
  Bottom Layer w7.1: v1(4870.5,4769.5) 4940.5,4769.5 5280.5,4429.5 5310.5,4429.5 v1(5330.5,4409.5)
$1N191: U1.55 U31.2 | length 1305.3
  Top Layer w7.8: U1.55@4603.2,5336.1 4603.2,5363.1 4613.2,5373.1 4613.2,5403.1 v1(4603.2,5413.1)
  Bottom Layer w7.8: v1(4603.2,5413.1) 4758,5567.9 U31.2@5759.1,5567.9
$1N192: C24.1 U14.24 | length 531.5
  Top Layer w8.5: v1(4691.4,4667.8) C24.1@4691.4,4695.7 ; v1(4941.4,4297.8) U14.24@4941.4,4327.8
  Inner1 w8.5: v1(4691.4,4667.8) 4691.4,4547.8 v1(4941.4,4297.8)
$1N193: C23.1 U14.21 | length 247.2
  Top Layer w8.5: v1(4870.6,4525.9) 4870.6,4565.9 C23.1@4871.2,4566.5 ; U14.21@4890.6,4327.8 v1(4890.6,4385.9)
  Inner1 w8.5: v1(4870.6,4525.9) 4890.6,4505.9 v1(4890.6,4385.9)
